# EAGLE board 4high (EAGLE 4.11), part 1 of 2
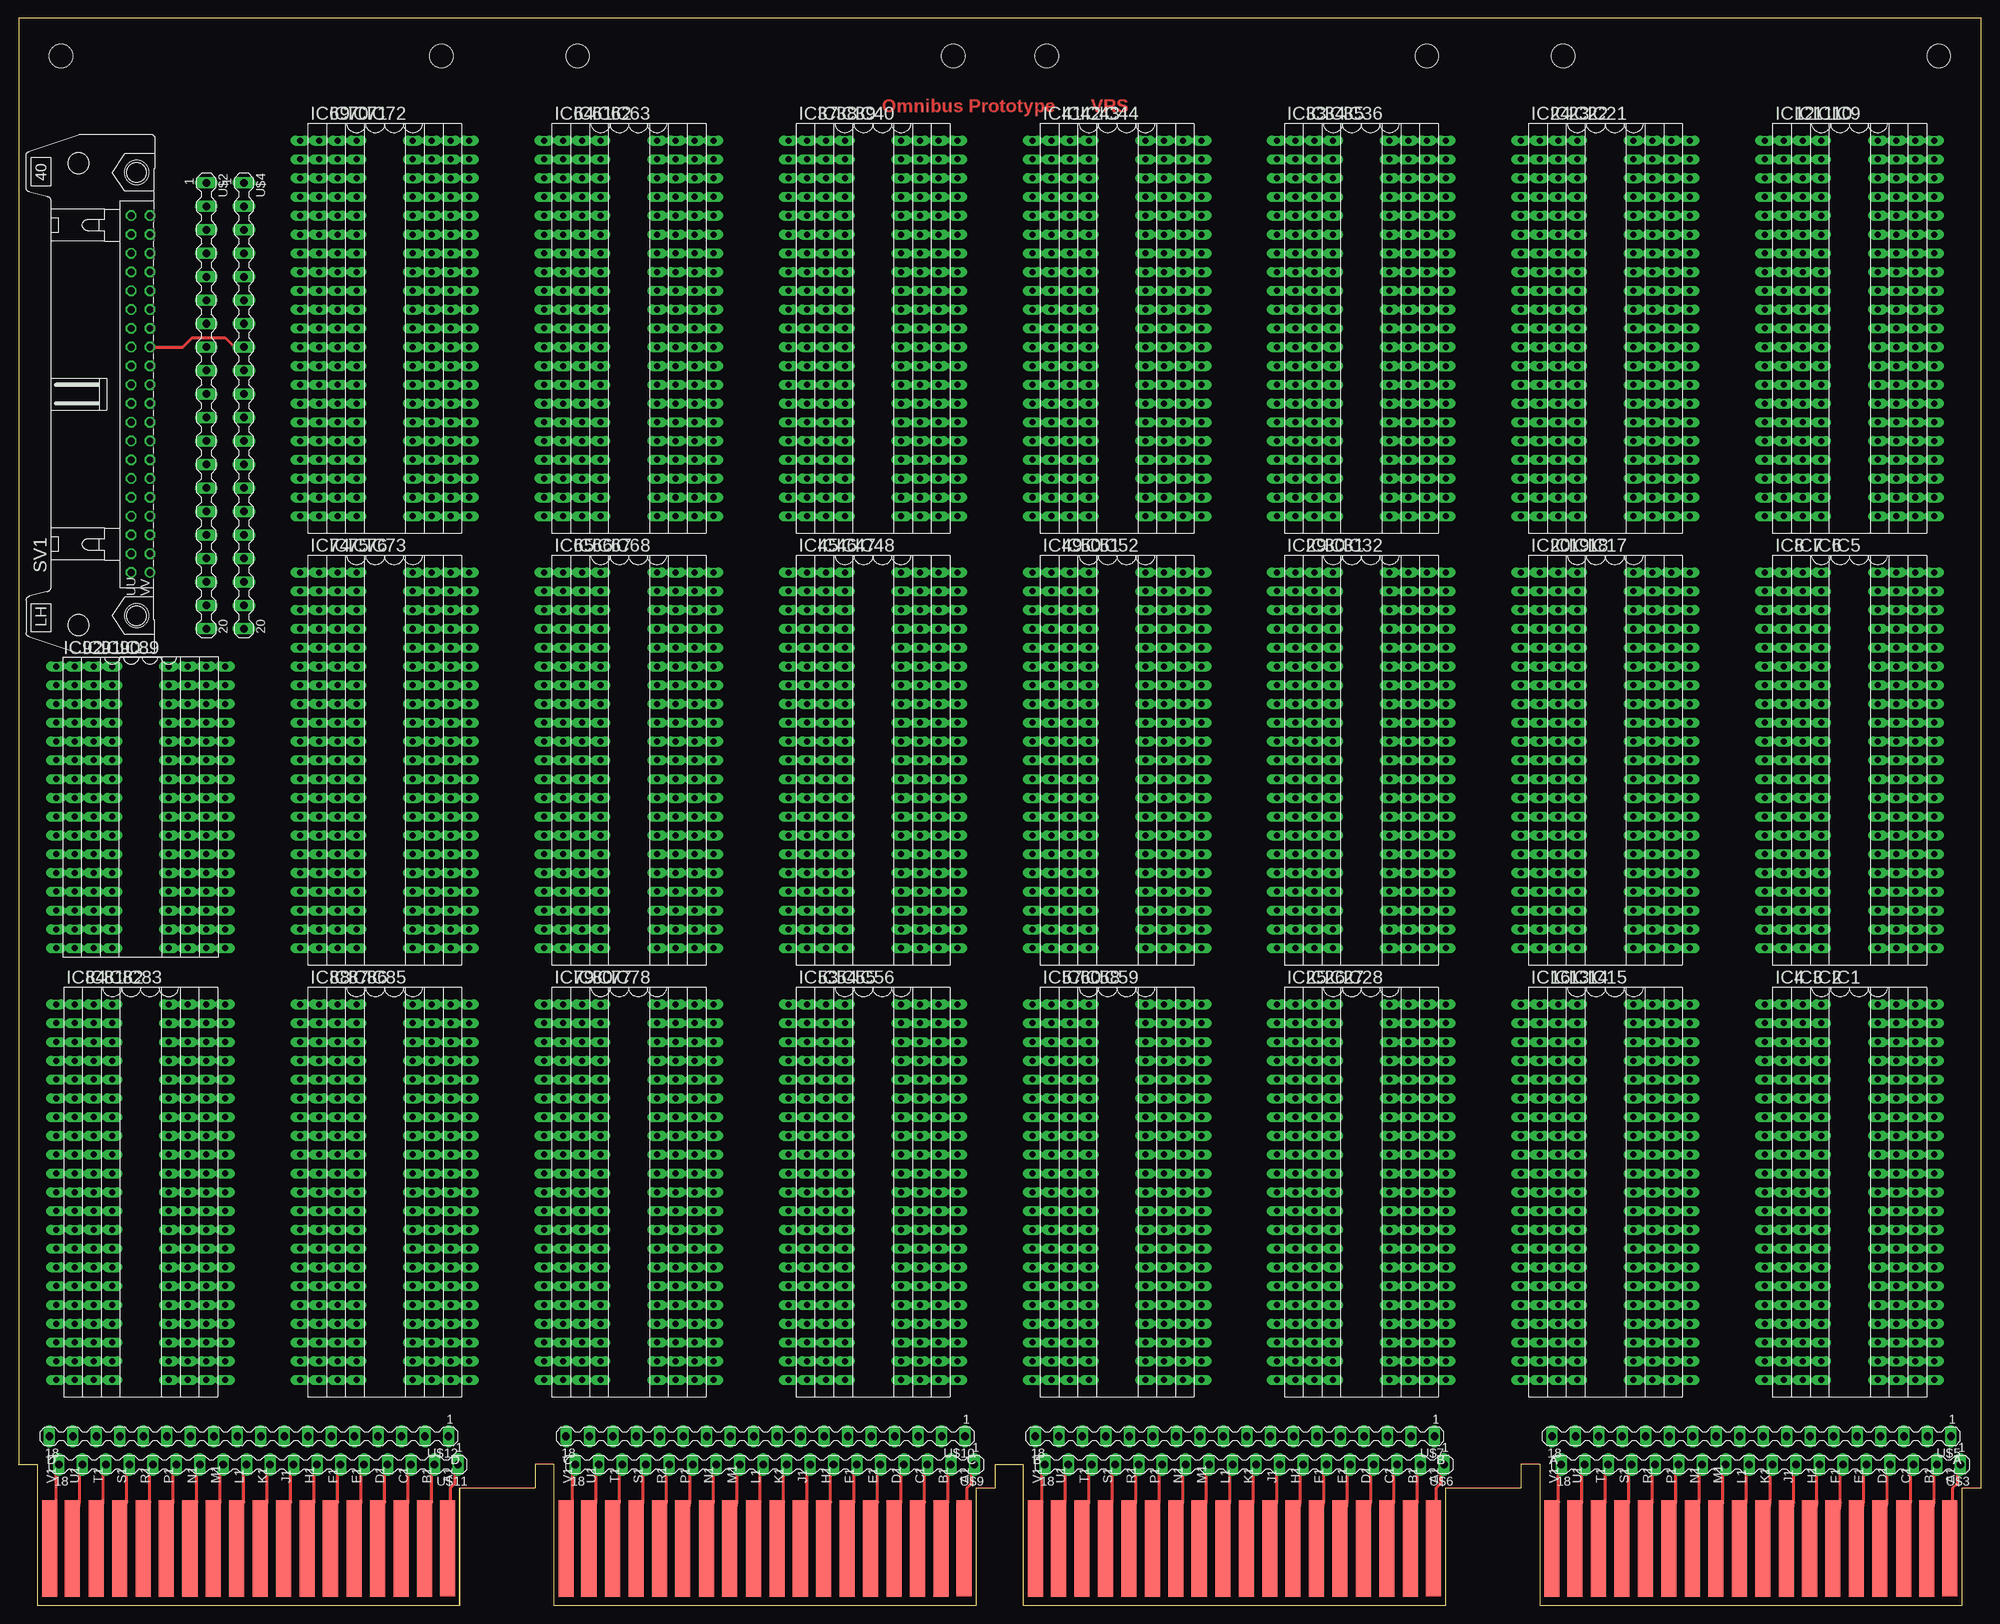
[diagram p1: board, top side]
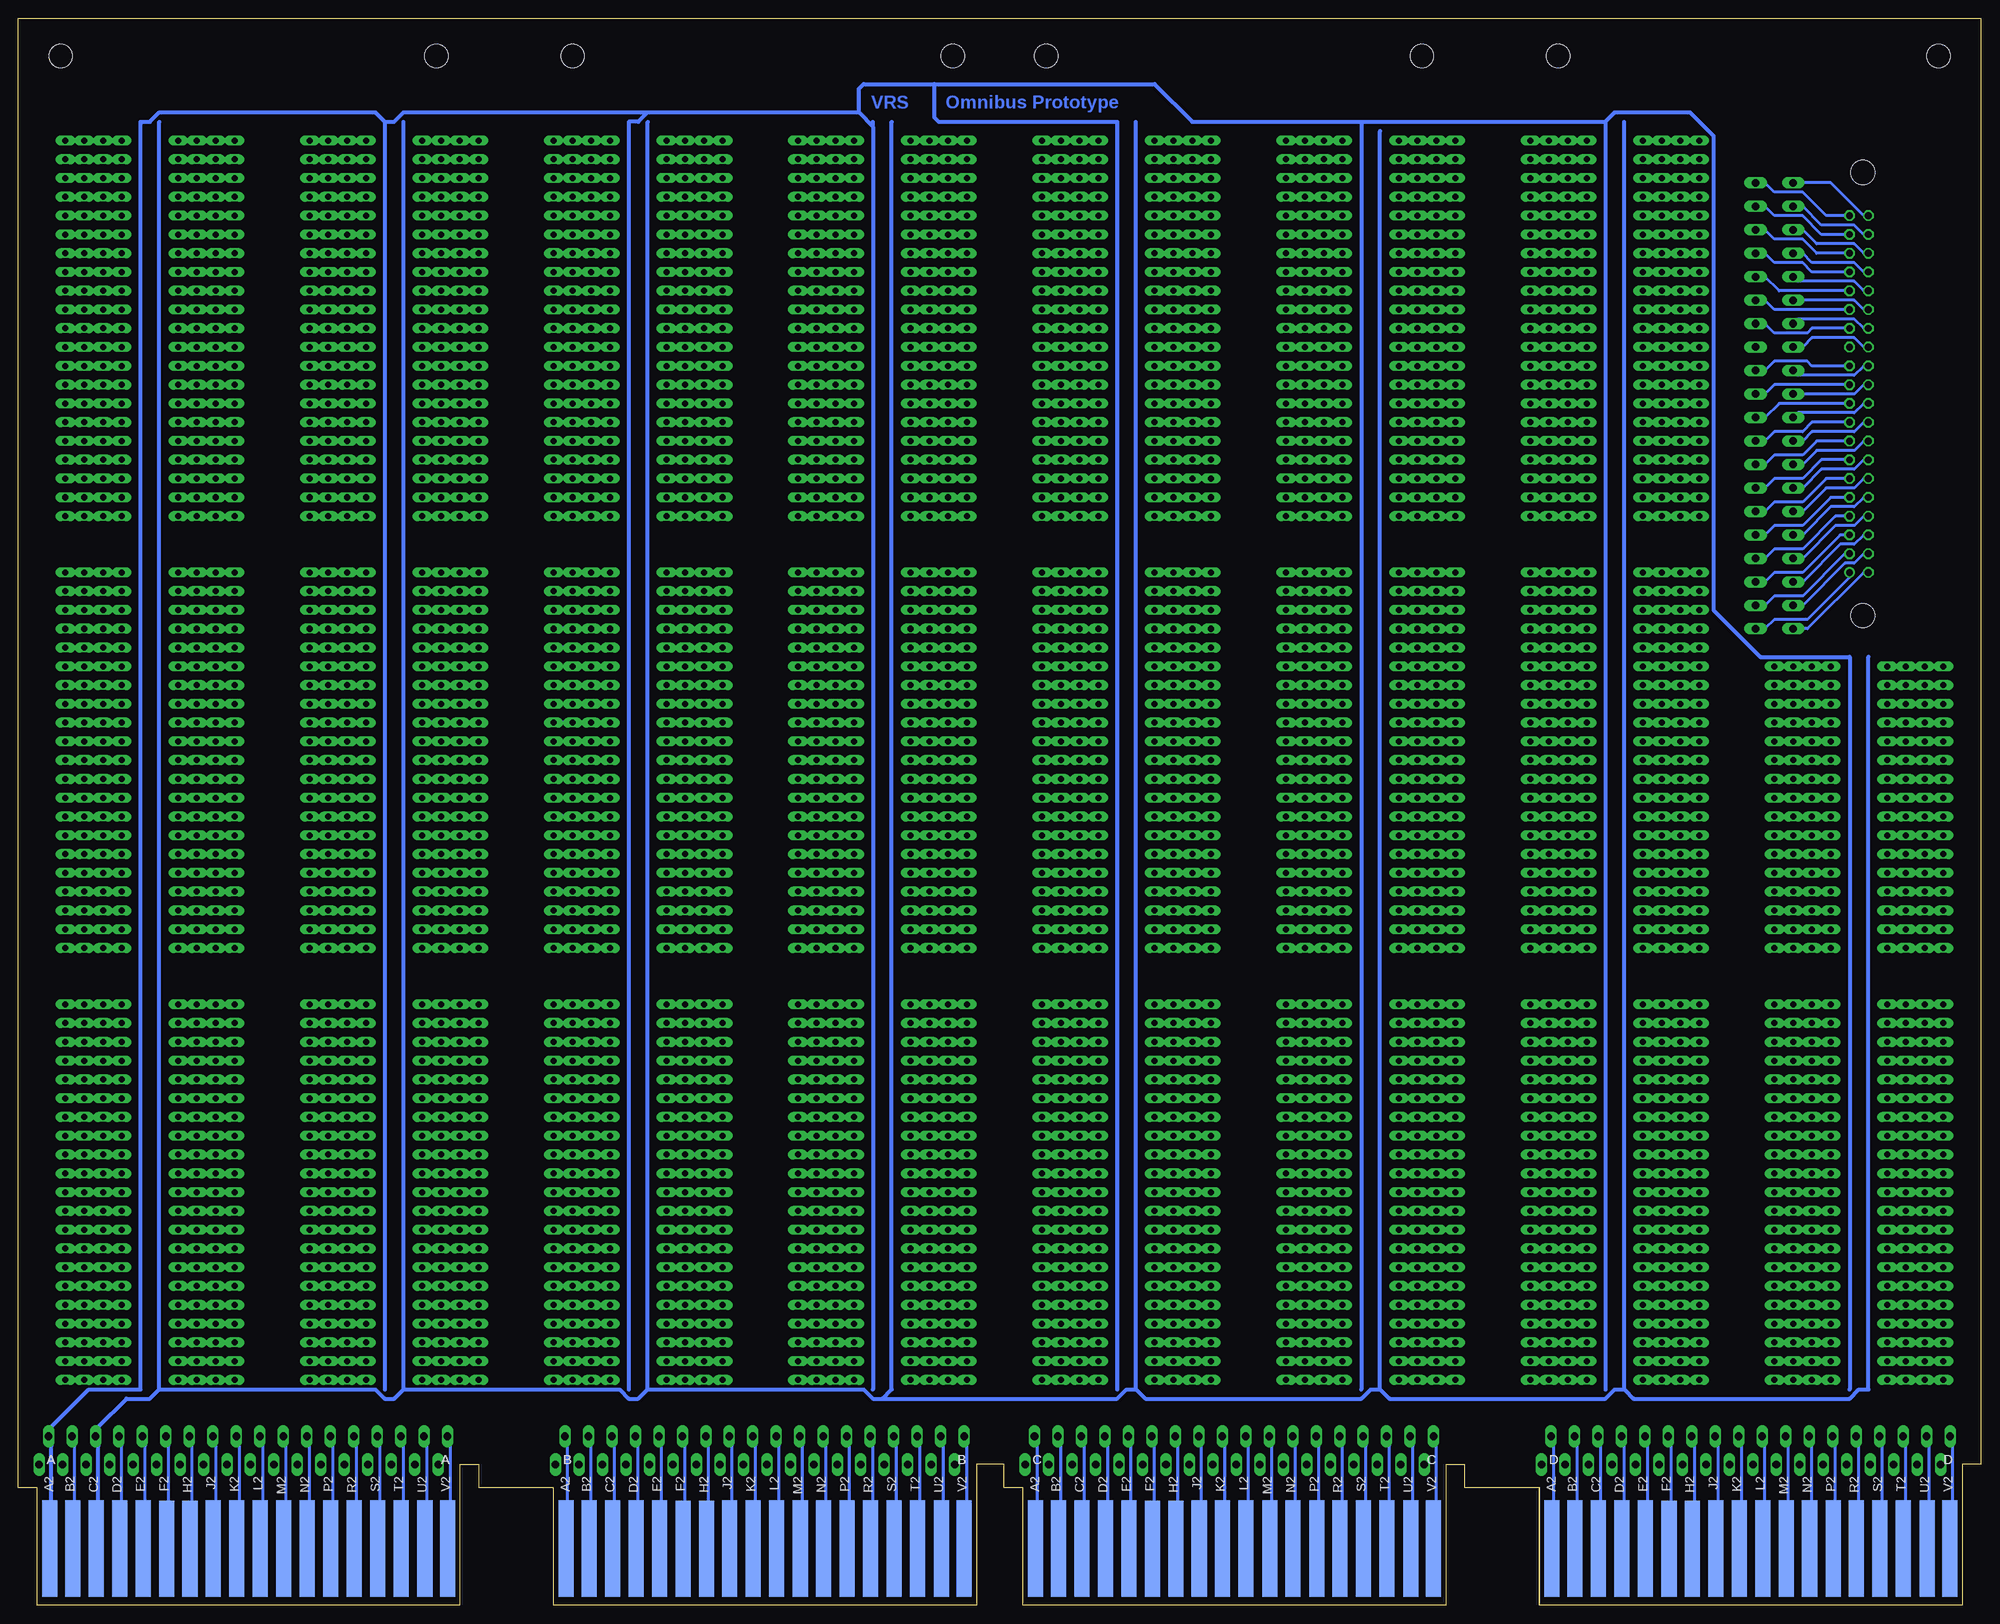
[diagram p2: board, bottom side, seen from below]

Size 265.43 x 214.63 mm. Coordinates in mm from the lower left corner, seen from the top.
Copper layers (1*16): Top 0.035mm / dielectric 1.5mm / Bottom 0.035mm
Design rules "olimex10mil": minimum track width 15mil, minimum drill 24mil, track to track 15mil, track to pad 10mil, pad to pad 10mil, via to via 10mil, smd to smd 10mil, copper to edge 25mil, drill to drill 10mil, minimum pad ring 10mil, minimum via ring 8mil, stop-mask expansion 0mil, vias tented up to drill 0mil, thermal gap 10mil
Net classes: 1 supply: width 0.508 mm

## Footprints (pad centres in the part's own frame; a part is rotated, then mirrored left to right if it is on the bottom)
DIL42 = drill 0.813 long: 1 -25.4,-7.62; 2 -22.86,-7.62; 3 -20.32,-7.62; 4 -17.78,-7.62; 5 -15.24,-7.62; 6 -12.7,-7.62; 7 -10.16,-7.62; 8 -7.62,-7.62; 9 -5.08,-7.62; 10 -2.54,-7.62; 11 0,-7.62; 12 2.54,-7.62; 13 5.08,-7.62; 14 7.62,-7.62; 15 10.16,-7.62; 16 12.7,-7.62; 17 15.24,-7.62; 18 17.78,-7.62; 19 20.32,-7.62; 20 22.86,-7.62; 21 25.4,-7.62; 22 25.4,7.62; 23 22.86,7.62; 24 20.32,7.62; 25 17.78,7.62; 26 15.24,7.62; 27 12.7,7.62; 28 10.16,7.62; 29 7.62,7.62; 30 5.08,7.62; 31 2.54,7.62; 32 0,7.62; 33 -2.54,7.62; 34 -5.08,7.62; 35 -7.62,7.62; 36 -10.16,7.62; 37 -12.7,7.62; 38 -15.24,7.62; 39 -17.78,7.62; 40 -20.32,7.62; 41 -22.86,7.62; 42 -25.4,7.62
DIL32 = drill 0.813 long: 1 -19.05,-7.62; 2 -16.51,-7.62; 3 -13.97,-7.62; 4 -11.43,-7.62; 5 -8.89,-7.62; 6 -6.35,-7.62; 7 -3.81,-7.62; 8 -1.27,-7.62; 9 1.27,-7.62; 10 3.81,-7.62; 11 6.35,-7.62; 12 8.89,-7.62; 13 11.43,-7.62; 14 13.97,-7.62; 15 16.51,-7.62; 16 19.05,-7.62; 17 19.05,7.62; 18 16.51,7.62; 19 13.97,7.62; 20 11.43,7.62; 21 8.89,7.62; 22 6.35,7.62; 23 3.81,7.62; 24 1.27,7.62; 25 -1.27,7.62; 26 -3.81,7.62; 27 -6.35,7.62; 28 -8.89,7.62; 29 -11.43,7.62; 30 -13.97,7.62; 31 -16.51,7.62; 32 -19.05,7.62
DEC40PINH = drill 0.914 octagon: A 24.13,1.27; AA -3.81,1.27; B 24.13,-1.27; BB -3.81,-1.27; C 21.59,1.27; CC -6.35,1.27; D 21.59,-1.27; DD -6.35,-1.27; E 19.05,1.27; EE -8.89,1.27; F 19.05,-1.27; FF -8.89,-1.27; H 16.51,1.27; HH -11.43,1.27; J 16.51,-1.27; JJ -11.43,-1.27; K 13.97,1.27; KK -13.97,1.27; L 13.97,-1.27; LL -13.97,-1.27; M 11.43,1.27; MM -16.51,1.27; N 11.43,-1.27; NN -16.51,-1.27; P 8.89,1.27; PP -19.05,1.27; R 8.89,-1.27; RR -19.05,-1.27; S 6.35,1.27; SS -21.59,1.27; T 6.35,-1.27; TT -21.59,-1.27; U 3.81,1.27; UU -24.13,1.27; V 3.81,-1.27; W 1.27,1.27; X 1.27,-1.27; Y -1.27,1.27; Z -1.27,-1.27 | drill 0.914 round: VV -24.13,-1.27 | hole 3.302: -29.972,0.533; 29.972,0.533
EDGE-CON8 = smd 2.032 x 13.017: AA1 261.223,7.709; AB1 258.118,7.684; AC1 254.956,7.684; AD1 251.765,7.684; AE1 248.59,7.693; AF1 245.389,7.668; AH1 242.24,7.668; AJ1 239.09,7.668; AK1 235.915,7.668; AL1 232.74,7.693; AM1 229.54,7.693; AN1 226.39,7.693; AP1 223.19,7.668; AR1 220.04,7.668; AS1 216.865,7.693; AT1 213.69,7.693; AU1 210.49,7.693; AV1 207.404,7.668; BA1 191.373,7.709; BB1 188.268,7.684; BC1 185.106,7.684; BD1 181.915,7.684; BE1 178.74,7.693; BF1 175.539,7.668; BH1 172.39,7.668; BJ1 169.24,7.668; BK1 166.065,7.668; BL1 162.89,7.693; BM1 159.69,7.693; BN1 156.54,7.693; BP1 153.34,7.668; BR1 150.19,7.668; BS1 147.015,7.693; BT1 143.84,7.693; BU1 140.64,7.693; BV1 137.554,7.668; CA1 127.873,7.709; CB1 124.768,7.684; CC1 121.606,7.684; CD1 118.415,7.684; CE1 115.24,7.693; CF1 112.039,7.668; CH1 108.89,7.668; CJ1 105.74,7.668; CK1 102.565,7.668; CL1 99.39,7.693; CM1 96.19,7.693; CN1 93.04,7.693; CP1 89.84,7.668; CR1 86.69,7.668; CS1 83.515,7.693; CT1 80.34,7.693; CU1 77.14,7.693; CV1 74.054,7.668; DA1 58.023,7.709; DB1 54.918,7.684; DC1 51.756,7.684; DD1 48.565,7.684; DE1 45.39,7.693; DF1 42.189,7.668; DH1 39.04,7.668; DJ1 35.89,7.668; DK1 32.715,7.668; DL1 29.54,7.693; DM1 26.34,7.693; DN1 23.19,7.693; DP1 19.99,7.668; DR1 16.84,7.668; DS1 13.665,7.693; DT1 10.49,7.693; DU1 7.29,7.693; DV1 4.204,7.668 | smd 2.032 x 13.017 bottom: AA2 261.223,7.69; AB2 258.102,7.668; AC2 254.94,7.668; AD2 251.765,7.693; AE2 248.59,7.693; AF2 245.389,7.642; AH2 242.24,7.642; AJ2 239.09,7.668; AK2 235.915,7.668; AL2 232.74,7.693; AM2 229.54,7.693; AN2 226.39,7.693; AP2 223.19,7.668; AR2 220.04,7.668; AS2 216.865,7.693; AT2 213.69,7.693; AU2 210.464,7.693; AV2 207.404,7.668; BA2 191.373,7.69; BB2 188.252,7.668; BC2 185.09,7.668; BD2 181.915,7.693; BE2 178.74,7.693; BF2 175.539,7.642; BH2 172.39,7.642; BJ2 169.24,7.668; BK2 166.065,7.668; BL2 162.89,7.693; BM2 159.69,7.693; BN2 156.54,7.693; BP2 153.34,7.668; BR2 150.19,7.668; BS2 147.015,7.693; BT2 143.84,7.693; BU2 140.614,7.693; BV2 137.554,7.668; CA2 127.873,7.69; CB2 124.752,7.668; CC2 121.59,7.668; CD2 118.415,7.693; CE2 115.24,7.693; CF2 112.039,7.642; CH2 108.89,7.642; CJ2 105.74,7.668; CK2 102.565,7.668; CL2 99.39,7.693; CM2 96.19,7.693; CN2 93.04,7.693; CP2 89.84,7.668; CR2 86.69,7.668; CS2 83.515,7.693; CT2 80.34,7.693; CU2 77.114,7.693; CV2 74.054,7.668; DA2 58.023,7.69; DB2 54.902,7.668; DC2 51.74,7.668; DD2 48.565,7.693; DE2 45.39,7.693; DF2 42.189,7.642; DH2 39.04,7.642; DJ2 35.89,7.668; DK2 32.715,7.668; DL2 29.54,7.693; DM2 26.34,7.693; DN2 23.19,7.693; DP2 19.99,7.668; DR2 16.84,7.668; DS2 13.665,7.693; DT2 10.49,7.693; DU2 7.264,7.693; DV2 4.204,7.668
MA20-1 = drill 1.016 long: 1 -28.575,0; 2 -25.4,0; 3 -22.225,0; 4 -19.05,0; 5 -15.875,0; 6 -12.7,0; 7 -9.525,0; 8 -6.35,0; 9 -3.175,0; 10 0,0; 11 3.175,0; 12 6.35,0; 13 9.525,0; 14 12.7,0; 15 15.875,0; 16 19.05,0; 17 22.225,0; 18 25.4,0; 19 28.575,0; 20 31.75,0
MA18-1 = drill 1.016 long: 1 -25.146,0; 2 -21.971,0; 3 -18.796,0; 4 -15.621,0; 5 -12.446,0; 6 -9.271,0; 7 -6.096,0; 8 -2.921,0; 9 0.254,0; 10 3.429,0; 11 6.604,0; 12 9.779,0; 13 12.954,0; 14 16.129,0; 15 19.304,0; 16 22.479,0; 17 25.654,0; 18 28.829,0
OMNIBUS = hole 3.175: 208.915,209.55; 259.715,209.55; 190.5,209.55; 139.065,209.55; 75.616,209.55; 126.416,209.55; 57.201,209.55; 5.766,209.55

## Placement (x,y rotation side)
IC1  [DIL42]  251.46,55.88 270 top
IC2  [DIL42]  248.92,55.88 270 top
IC3  [DIL42]  246.38,55.88 270 top
IC4  [DIL42]  243.84,55.88 270 top
IC5  [DIL42]  251.46,114.3 270 top
IC6  [DIL42]  248.92,114.3 270 top
IC7  [DIL42]  246.38,114.3 270 top
IC8  [DIL42]  243.84,114.3 270 top
IC9  [DIL42]  251.46,172.72 270 top
IC10  [DIL42]  248.92,172.72 270 top
IC11  [DIL42]  246.38,172.72 270 top
IC12  [DIL42]  243.84,172.72 270 top
IC13  [DIL42]  213.36,55.88 270 top
IC14  [DIL42]  215.9,55.88 270 top
IC15  [DIL42]  218.44,55.88 270 top
IC16  [DIL42]  210.82,55.88 270 top
IC17  [DIL42]  218.44,114.3 270 top
IC18  [DIL42]  215.9,114.3 270 top
IC19  [DIL42]  213.36,114.3 270 top
IC20  [DIL42]  210.82,114.3 270 top
IC21  [DIL42]  218.44,172.72 270 top
IC22  [DIL42]  215.9,172.72 270 top
IC23  [DIL42]  213.36,172.72 270 top
IC24  [DIL42]  210.82,172.72 270 top
IC25  [DIL42]  177.8,55.88 270 top
IC26  [DIL42]  180.34,55.88 270 top
IC27  [DIL42]  182.88,55.88 270 top
IC28  [DIL42]  185.42,55.88 270 top
IC29  [DIL42]  177.8,114.3 270 top
IC30  [DIL42]  180.34,114.3 270 top
IC31  [DIL42]  182.88,114.3 270 top
IC32  [DIL42]  185.42,114.3 270 top
IC33  [DIL42]  177.8,172.72 270 top
IC34  [DIL42]  180.34,172.72 270 top
IC35  [DIL42]  182.88,172.72 270 top
IC36  [DIL42]  185.42,172.72 270 top
IC37  [DIL42]  111.76,172.72 270 top
IC38  [DIL42]  114.3,172.72 270 top
IC39  [DIL42]  116.84,172.72 270 top
IC40  [DIL42]  119.38,172.72 270 top
IC41  [DIL42]  144.78,172.72 270 top
IC42  [DIL42]  147.32,172.72 270 top
IC43  [DIL42]  149.86,172.72 270 top
IC44  [DIL42]  152.4,172.72 270 top
IC45  [DIL42]  111.76,114.3 270 top
IC46  [DIL42]  114.3,114.3 270 top
IC47  [DIL42]  116.84,114.3 270 top
IC48  [DIL42]  119.38,114.3 270 top
IC49  [DIL42]  144.78,114.3 270 top
IC50  [DIL42]  147.32,114.3 270 top
IC51  [DIL42]  149.86,114.3 270 top
IC52  [DIL42]  152.4,114.3 270 top
IC53  [DIL42]  111.76,55.88 270 top
IC54  [DIL42]  114.3,55.88 270 top
IC55  [DIL42]  116.84,55.88 270 top
IC56  [DIL42]  119.38,55.88 270 top
IC57  [DIL42]  144.78,55.88 270 top
IC58  [DIL42]  149.86,55.88 270 top
IC59  [DIL42]  152.4,55.88 270 top
IC60  [DIL42]  147.32,55.88 270 top
IC61  [DIL42]  81.28,172.72 270 top
IC62  [DIL42]  83.82,172.72 270 top
IC63  [DIL42]  86.36,172.72 270 top
IC64  [DIL42]  78.74,172.72 270 top
IC65  [DIL42]  78.74,114.3 270 top
IC66  [DIL42]  81.28,114.3 270 top
IC67  [DIL42]  83.82,114.3 270 top
IC68  [DIL42]  86.36,114.3 270 top
IC69  [DIL42]  45.72,172.72 270 top
IC70  [DIL42]  48.26,172.72 270 top
IC71  [DIL42]  50.8,172.72 270 top
IC72  [DIL42]  53.34,172.72 270 top
IC73  [DIL42]  53.34,114.3 270 top
IC74  [DIL42]  45.72,114.3 270 top
IC75  [DIL42]  48.26,114.3 270 top
IC76  [DIL42]  50.8,114.3 270 top
IC77  [DIL42]  83.82,55.88 270 top
IC78  [DIL42]  86.36,55.88 270 top
IC79  [DIL42]  78.74,55.88 270 top
IC80  [DIL42]  81.28,55.88 270 top
IC81  [DIL42]  15.24,55.88 270 top
IC82  [DIL42]  17.78,55.88 270 top
IC83  [DIL42]  20.32,55.88 270 top
IC84  [DIL42]  12.7,55.88 270 top
IC85  [DIL42]  53.34,55.88 270 top
IC86  [DIL42]  50.8,55.88 270 top
IC87  [DIL42]  48.26,55.88 270 top
IC88  [DIL42]  45.72,55.88 270 top
IC89  [DIL32]  20.32,107.95 270 top
IC90  [DIL32]  17.78,107.95 270 top
IC91  [DIL32]  15.24,107.95 270 top
IC92  [DIL32]  12.7,107.95 270 top
SV1  [DEC40PINH]  16.51,163.83 90 top
U$1  [EDGE-CON8]  0,0 0 top
U$2  MA20-1  [MA20-1]  25.4,163.83 270 top
U$3  MA18-1  [MA18-1]  237.49,19.05 180 top
U$4  MA20-1  [MA20-1]  30.48,163.83 270 top
U$5  MA18-1  [MA18-1]  236.22,22.86 180 top
U$6  MA18-1  [MA18-1]  167.64,19.05 180 top
U$7  MA18-1  [MA18-1]  166.37,22.86 180 top
U$8  OUTLINE-OMNIBUS  [OMNIBUS]  0,0 0 top
U$9  MA18-1  [MA18-1]  104.14,19.05 180 top
U$10  MA18-1  [MA18-1]  102.87,22.86 180 top
U$11  MA18-1  [MA18-1]  34.29,19.05 180 top
U$12  MA18-1  [MA18-1]  33.02,22.86 180 top

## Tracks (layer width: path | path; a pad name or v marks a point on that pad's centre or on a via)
GND
  Bottom 0.508: U$1.AC2 254.63,13.97 254.63,21.59 U$5.3 254.63,24.13 250.82,27.94 247.65,27.94 246.38,29.21 | 15.24,128.27 15.24,29.21 16.51,29.21 17.78,27.94 46.99,27.94 48.26,29.21 | 48.26,29.21 48.26,200.66 | 81.28,29.21 81.28,199.39 | 114.3,29.21 114.3,200.66 | 147.32,200.66 147.32,29.21 148.59,27.94 | 180.34,29.21 180.34,200.66 | 213.36,29.21 213.36,200.66 | 246.38,29.21 246.38,200.66 | 48.26,29.21 49.53,29.21 50.8,27.94 80.01,27.94 81.28,29.21 | 81.28,29.21 82.55,29.21 83.82,27.94 113.03,27.94 114.3,29.21 | 246.38,29.21 217.17,29.21 215.9,27.94 214.63,27.94 213.36,29.21 | 213.36,29.21 184.15,29.21 182.88,27.94 181.61,27.94 180.34,29.21 | 180.34,29.21 151.13,29.21 149.86,27.94 148.59,27.94 | 114.3,29.21 115.57,29.21 116.84,27.94 148.59,27.94
N$1
  Bottom 0.381: IC4.1 IC3.1 IC2.1 IC1.1
N$2
  Bottom 0.381: IC4.2 IC3.2 IC2.2 IC1.2
N$3
  Bottom 0.381: IC4.3 IC3.3 IC2.3 IC1.3
N$4
  Bottom 0.381: IC4.4 IC3.4 IC2.4 IC1.4
N$5
  Bottom 0.381: IC4.5 IC3.5 IC2.5 IC1.5
N$6
  Bottom 0.381: IC4.6 IC3.6 IC2.6 IC1.6
N$7
  Bottom 0.381: IC4.7 IC3.7 IC2.7 IC1.7
N$8
  Bottom 0.381: IC4.8 IC3.8 IC2.8 IC1.8
N$9
  Bottom 0.381: IC4.9 IC3.9 IC2.9 IC1.9
N$10
  Bottom 0.381: IC4.10 IC3.10 IC2.10 IC1.10
N$11
  Bottom 0.381: IC4.11 IC3.11 IC2.11 IC1.11
N$12
  Bottom 0.381: IC4.12 IC3.12 IC2.12 IC1.12
N$13
  Bottom 0.381: IC4.13 IC3.13 IC2.13 IC1.13
N$14
  Bottom 0.381: IC4.14 IC3.14 IC2.14 IC1.14
N$15
  Bottom 0.381: IC4.15 IC3.15 IC2.15 IC1.15
N$16
  Bottom 0.381: IC4.16 IC3.16 IC2.16 IC1.16
N$17
  Bottom 0.381: IC4.17 IC3.17 IC2.17 IC1.17
N$18
  Bottom 0.381: IC4.18 IC3.18 IC2.18 IC1.18
N$19
  Bottom 0.381: IC4.19 IC3.19 IC2.19 IC1.19
N$20
  Bottom 0.381: IC4.20 IC3.20 IC2.20 IC1.20
N$21
  Bottom 0.381: IC4.21 IC3.21 IC2.21 IC1.21
N$22
  Bottom 0.381: IC4.22 IC3.22 IC2.22 IC1.22
N$23
  Bottom 0.381: IC4.23 IC3.23 IC2.23 IC1.23
N$24
  Bottom 0.381: IC4.24 IC3.24 IC2.24 IC1.24
N$25
  Bottom 0.381: IC4.25 IC3.25 IC2.25 IC1.25
N$26
  Bottom 0.381: IC4.26 IC3.26 IC2.26 IC1.26
N$27
  Bottom 0.381: IC4.27 IC3.27 IC2.27 IC1.27
N$28
  Bottom 0.381: IC4.28 IC3.28 IC2.28 IC1.28
N$29
  Bottom 0.381: IC4.29 IC3.29 IC2.29 IC1.29
N$30
  Bottom 0.381: IC4.30 IC3.30 IC2.30 IC1.30
N$31
  Bottom 0.381: IC4.31 IC3.31 IC2.31 IC1.31
N$32
  Bottom 0.381: IC4.32 IC3.32 IC2.32 IC1.32
N$33
  Bottom 0.381: IC4.33 IC3.33 IC2.33 IC1.33
N$34
  Bottom 0.381: IC4.34 IC3.34 IC2.34 IC1.34
N$35
  Bottom 0.381: IC4.35 IC3.35 IC2.35 IC1.35
N$36
  Bottom 0.381: IC4.36 IC3.36 IC2.36 IC1.36
N$37
  Bottom 0.381: IC4.37 IC3.37 IC2.37 IC1.37
N$38
  Bottom 0.381: IC4.38 IC3.38 IC2.38 IC1.38
N$39
  Bottom 0.381: IC4.39 IC3.39 IC2.39 IC1.39
N$40
  Bottom 0.381: IC4.40 IC3.40 IC2.40 IC1.40
N$41
  Bottom 0.381: IC4.41 IC3.41 IC2.41 IC1.41
N$42
  Bottom 0.381: IC4.42 IC3.42 IC2.42 IC1.42
N$43
  Bottom 0.381: IC8.1 IC7.1 IC6.1 IC5.1
N$44
  Bottom 0.381: IC8.2 IC7.2 IC6.2 IC5.2
N$45
  Bottom 0.381: IC8.3 IC7.3 IC6.3 IC5.3
N$46
  Bottom 0.381: IC8.4 IC7.4 IC6.4 IC5.4
N$47
  Bottom 0.381: IC8.5 IC7.5 IC6.5 IC5.5
N$48
  Bottom 0.381: IC8.6 IC7.6 IC6.6 IC5.6
N$49
  Bottom 0.381: IC8.7 IC7.7 IC6.7 IC5.7
N$50
  Bottom 0.381: IC8.8 IC7.8 IC6.8 IC5.8
N$51
  Bottom 0.381: IC8.9 IC7.9 IC6.9 IC5.9
N$52
  Bottom 0.381: IC8.10 IC7.10 IC6.10 IC5.10
N$53
  Bottom 0.381: IC8.11 IC7.11 IC6.11 IC5.11
N$54
  Bottom 0.381: IC8.12 IC7.12 IC6.12 IC5.12
N$55
  Bottom 0.381: IC8.13 IC7.13 IC6.13 IC5.13
N$56
  Bottom 0.381: IC8.14 IC7.14 IC6.14 IC5.14
N$57
  Bottom 0.381: IC8.15 IC7.15 IC6.15 IC5.15
N$58
  Bottom 0.381: IC8.16 IC7.16 IC6.16 IC5.16
N$59
  Bottom 0.381: IC8.17 IC7.17 IC6.17 IC5.17
N$60
  Bottom 0.381: IC8.18 IC7.18 IC6.18 IC5.18
N$61
  Bottom 0.381: IC8.19 IC7.19 IC6.19 IC5.19
N$62
  Bottom 0.381: IC8.20 IC7.20 IC6.20 IC5.20
N$63
  Bottom 0.381: IC8.21 IC7.21 IC6.21 IC5.21
N$64
  Bottom 0.381: IC8.22 IC7.22 IC6.22 IC5.22
N$65
  Bottom 0.381: IC8.23 IC7.23 IC6.23 IC5.23
N$66
  Bottom 0.381: IC8.24 IC7.24 IC6.24 IC5.24
N$67
  Bottom 0.381: IC8.25 IC7.25 IC6.25 IC5.25
N$68
  Bottom 0.381: IC8.26 IC7.26 IC6.26 IC5.26
N$69
  Bottom 0.381: IC8.27 IC7.27 IC6.27 IC5.27
N$70
  Bottom 0.381: IC8.28 IC7.28 IC6.28 IC5.28
N$71
  Bottom 0.381: IC8.29 IC7.29 IC6.29 IC5.29
N$72
  Bottom 0.381: IC8.30 IC7.30 IC6.30 IC5.30
N$73
  Bottom 0.381: IC8.31 IC7.31 IC6.31 IC5.31
N$74
  Bottom 0.381: IC8.32 IC7.32 IC6.32 IC5.32
N$75
  Bottom 0.381: IC8.33 IC7.33 IC6.33 IC5.33
N$76
  Bottom 0.381: IC8.34 IC7.34 IC6.34 IC5.34
N$77
  Bottom 0.381: IC8.35 IC7.35 IC6.35 IC5.35
N$78
  Bottom 0.381: IC8.36 IC7.36 IC6.36 IC5.36
N$79
  Bottom 0.381: IC8.37 IC7.37 IC6.37 IC5.37
N$80
  Bottom 0.381: IC8.38 IC7.38 IC6.38 IC5.38
N$81
  Bottom 0.381: IC8.39 IC7.39 IC6.39 IC5.39
N$82
  Bottom 0.381: IC8.40 IC7.40 IC6.40 IC5.40
N$83
  Bottom 0.381: IC8.41 IC7.41 IC6.41 IC5.41
N$84
  Bottom 0.381: IC8.42 IC7.42 IC6.42 IC5.42
N$85
  Bottom 0.381: IC12.1 IC11.1 IC10.1 IC9.1
N$86
  Bottom 0.381: IC12.2 IC11.2 IC10.2 IC9.2
N$87
  Bottom 0.381: IC12.3 IC11.3 IC10.3 IC9.3
N$88
  Bottom 0.381: IC12.4 IC11.4 IC10.4 IC9.4
N$89
  Bottom 0.381: IC12.5 IC11.5 IC10.5 IC9.5
N$90
  Bottom 0.381: IC12.6 IC11.6 IC10.6 IC9.6
N$91
  Bottom 0.381: IC12.7 IC11.7 IC10.7 IC9.7
N$92
  Bottom 0.381: IC12.8 IC11.8 IC10.8 IC9.8
N$93
  Bottom 0.381: IC12.9 IC11.9 IC10.9 IC9.9
N$94
  Bottom 0.381: IC12.10 IC11.10 IC10.10 IC9.10
N$95
  Bottom 0.381: IC12.11 IC11.11 IC10.11 IC9.11
N$96
  Bottom 0.381: IC12.12 IC11.12 IC10.12 IC9.12
N$97
  Bottom 0.381: IC12.13 IC11.13 IC10.13 IC9.13
N$98
  Bottom 0.381: IC12.14 IC11.14 IC10.14 IC9.14
N$99
  Bottom 0.381: IC12.15 IC11.15 IC10.15 IC9.15
N$100
  Bottom 0.381: IC12.16 IC11.16 IC10.16 IC9.16
N$101
  Bottom 0.381: IC12.17 IC11.17 IC10.17 IC9.17
N$102
  Bottom 0.381: IC12.18 IC11.18 IC10.18 IC9.18
N$103
  Bottom 0.381: IC12.19 IC11.19 IC10.19 IC9.19
N$104
  Bottom 0.381: IC12.20 IC11.20 IC10.20 IC9.20
N$105
  Bottom 0.381: IC12.21 IC11.21 IC10.21 IC9.21
N$106
  Bottom 0.381: IC12.22 IC11.22 IC10.22 IC9.22
N$107
  Bottom 0.381: IC12.23 IC11.23 IC10.23 IC9.23
N$108
  Bottom 0.381: IC12.24 IC11.24 IC10.24 IC9.24
N$109
  Bottom 0.381: IC12.25 IC11.25 IC10.25 IC9.25
N$110
  Bottom 0.381: IC12.26 IC11.26 IC10.26 IC9.26
N$111
  Bottom 0.381: IC12.27 IC11.27 IC10.27 IC9.27
N$112
  Bottom 0.381: IC12.28 IC11.28 IC10.28 IC9.28
N$113
  Bottom 0.381: IC12.29 IC11.29 IC10.29 IC9.29
N$114
  Bottom 0.381: IC12.30 IC11.30 IC10.30 IC9.30
N$115
  Bottom 0.381: IC12.31 IC11.31 IC10.31 IC9.31
N$116
  Bottom 0.381: IC12.32 IC11.32 IC10.32 IC9.32
N$117
  Bottom 0.381: IC12.33 IC11.33 IC10.33 IC9.33
N$118
  Bottom 0.381: IC12.34 IC11.34 IC10.34 IC9.34
N$119
  Bottom 0.381: IC12.35 IC11.35 IC10.35 IC9.35
N$120
  Bottom 0.381: IC12.36 IC11.36 IC10.36 IC9.36
N$121
  Bottom 0.381: IC12.37 IC11.37 IC10.37 IC9.37
N$122
  Bottom 0.381: IC12.38 IC11.38 IC10.38 IC9.38
N$123
  Bottom 0.381: IC12.39 IC11.39 IC10.39 IC9.39
N$124
  Bottom 0.381: IC12.40 IC11.40 IC10.40 IC9.40
N$125
  Bottom 0.381: IC12.41 IC11.41 IC10.41 IC9.41
N$126
  Bottom 0.381: IC12.42 IC11.42 IC10.42 IC9.42
N$127
  Bottom 0.381: IC16.1 IC13.1 IC14.1 IC15.1
N$128
  Bottom 0.381: IC16.2 IC13.2 IC14.2 IC15.2
N$129
  Bottom 0.381: IC16.3 IC13.3 IC14.3 IC15.3
N$130
  Bottom 0.381: IC16.4 IC13.4 IC14.4 IC15.4
N$131
  Bottom 0.381: IC16.5 IC13.5 IC14.5 IC15.5
N$132
  Bottom 0.381: IC16.6 IC13.6 IC14.6 IC15.6
N$133
  Bottom 0.381: IC16.7 IC13.7 IC14.7 IC15.7
N$134
  Bottom 0.381: IC16.8 IC13.8 IC14.8 IC15.8
N$135
  Bottom 0.381: IC16.9 IC13.9 IC14.9 IC15.9
N$136
  Bottom 0.381: IC16.10 IC13.10 IC14.10 IC15.10
N$137
  Bottom 0.381: IC16.11 IC13.11 IC14.11 IC15.11
N$138
  Bottom 0.381: IC16.12 IC13.12 IC14.12 IC15.12
N$139
  Bottom 0.381: IC16.13 IC13.13 IC14.13 IC15.13
N$140
  Bottom 0.381: IC16.14 IC13.14 IC14.14 IC15.14
N$141
  Bottom 0.381: IC16.15 IC13.15 IC14.15 IC15.15
N$142
  Bottom 0.381: IC16.16 IC13.16 IC14.16 IC15.16
N$143
  Bottom 0.381: IC16.17 IC13.17 IC14.17 IC15.17
N$144
  Bottom 0.381: IC16.18 IC13.18 IC14.18 IC15.18
N$145
  Bottom 0.381: IC16.19 IC13.19 IC14.19 IC15.19
N$146
  Bottom 0.381: IC16.20 IC13.20 IC14.20 IC15.20
N$147
  Bottom 0.381: IC16.21 IC13.21 IC14.21 IC15.21
N$148
  Bottom 0.381: IC16.22 IC13.22 IC14.22 IC15.22
N$149
  Bottom 0.381: IC16.23 IC13.23 IC14.23 IC15.23
N$150
  Bottom 0.381: IC16.24 IC13.24 IC14.24 IC15.24
N$151
  Bottom 0.381: IC16.25 IC13.25 IC14.25 IC15.25
N$152
  Bottom 0.381: IC16.26 IC13.26 IC14.26 IC15.26
N$153
  Bottom 0.381: IC16.27 IC13.27 IC14.27 IC15.27
N$154
  Bottom 0.381: IC16.28 IC13.28 IC14.28 IC15.28
N$155
  Bottom 0.381: IC16.29 IC13.29 IC14.29 IC15.29
N$156
  Bottom 0.381: IC16.30 IC13.30 IC14.30 IC15.30
N$157
  Bottom 0.381: IC16.31 IC13.31 IC14.31 IC15.31
N$158
  Bottom 0.381: IC16.32 IC13.32 IC14.32 IC15.32
N$159
  Bottom 0.381: IC16.33 IC13.33 IC14.33 IC15.33
N$160
  Bottom 0.381: IC16.34 IC13.34 IC14.34 IC15.34
N$161
  Bottom 0.381: IC16.35 IC13.35 IC14.35 IC15.35
N$162
  Bottom 0.381: IC16.36 IC13.36 IC14.36 IC15.36
N$163
  Bottom 0.381: IC16.37 IC13.37 IC14.37 IC15.37
N$164
  Bottom 0.381: IC16.38 IC13.38 IC14.38 IC15.38
N$165
  Bottom 0.381: IC16.39 IC13.39 IC14.39 IC15.39
N$166
  Bottom 0.381: IC16.40 IC13.40 IC14.40 IC15.40
N$167
  Bottom 0.381: IC16.41 IC13.41 IC14.41 IC15.41
N$168
  Bottom 0.381: IC16.42 IC13.42 IC14.42 IC15.42
N$169
  Top 0.381: U$3.9 236.85,17.78 236.85,13.97 U$1.AK1
N$170
  Top 0.381: U$3.10 233.68,17.78 233.68,13.97 U$1.AL1
N$171
  Top 0.381: U$3.11 230.5,17.78 230.5,13.97 U$1.AM1
N$172
  Top 0.381: U$3.12 227.33,17.78 227.33,13.97 U$1.AN1
N$173
  Top 0.381: U$3.13 224.16,17.78 224.16,13.97 U$1.AP1
N$174
  Top 0.381: U$3.14 220.98,17.78 220.98,13.97 U$1.AR1
N$175
  Top 0.381: U$3.15 217.81,17.78 217.81,13.97 U$1.AS1
N$176
  Top 0.381: U$3.16 214.63,17.78 214.63,13.97 U$1.AT1
N$177
  Top 0.381: U$3.17 211.46,17.78 211.46,13.97 U$1.AU1
N$178
  Top 0.381: U$3.18 208.28,17.78 208.28,13.97 U$1.AV1
N$179
  Top 0.381: U$3.8 240.03,17.78 240.03,13.97 U$1.AJ1
N$180
  Top 0.381: U$3.7 243.21,17.78 243.21,13.97 U$1.AH1
N$181
  Top 0.381: U$3.6 246.38,17.78 246.38,13.97 U$1.AF1
N$182
  Top 0.381: U$3.5 249.56,17.78 249.56,13.97 U$1.AE1
N$183
  Top 0.381: U$3.4 252.73,17.78 252.73,13.97 U$1.AD1
N$184
  Top 0.381: U$3.3 255.91,17.78 255.91,13.97 U$1.AC1
N$185
  Top 0.381: U$3.2 259.08,17.78 259.08,13.97 U$1.AB1
N$186
  Top 0.381: U$3.1 262.25,17.78 262.25,16.51 261.62,15.88 261.62,13.97 U$1.AA1
N$187
  Bottom 0.381: U$5.10 232.41,21.59 232.41,13.97 U$1.AL2
N$188
  Bottom 0.381: U$5.11 229.24,21.59 229.24,13.97 U$1.AM2
N$189
  Bottom 0.381: U$5.12 226.06,21.59 226.06,13.97 U$1.AN2
N$190
  Bottom 0.381: U$5.13 222.88,21.59 222.88,13.97 U$1.AP2
N$191
  Bottom 0.381: U$5.14 219.71,21.59 219.71,13.97 U$1.AR2
N$192
  Bottom 0.381: U$5.15 216.53,21.59 216.53,13.97 U$1.AS2
N$193
  Bottom 0.381: U$5.16 213.36,21.59 213.36,13.97 U$1.AT2
N$194
  Bottom 0.381: U$5.9 235.59,21.59 235.59,13.97 U$1.AK2
N$195
  Bottom 0.381: U$5.8 238.76,21.59 238.76,13.97 U$1.AJ2
N$196
  Bottom 0.381: U$5.7 241.94,21.59 241.94,13.97 U$1.AH2
N$197
  Bottom 0.381: U$5.6 245.11,21.59 245.11,13.97 U$1.AF2
N$198
  Bottom 0.381: U$5.5 248.28,21.59 248.28,13.97 U$1.AE2
N$199
  Bottom 0.381: U$5.4 251.46,21.59 251.46,13.97 U$1.AD2
N$200
  Bottom 0.381: IC20.1 IC19.1 IC18.1 IC17.1
N$201
  Bottom 0.381: U$5.17 210.19,21.59 210.19,13.97 U$1.AU2
N$202
  Bottom 0.381: U$5.18 207.01,21.59 207.01,13.97 U$1.AV2
N$203
  Bottom 0.381: U$5.2 257.81,21.59 257.81,13.97 U$1.AB2
N$204
  Bottom 0.381: IC20.2 IC19.2 IC18.2 IC17.2
N$205
  Bottom 0.381: IC20.3 IC19.3 IC18.3 IC17.3
N$206
  Bottom 0.381: IC20.4 IC19.4 IC18.4 IC17.4
N$207
  Bottom 0.381: IC20.5 IC19.5 IC18.5 IC17.5
N$208
  Bottom 0.381: IC20.6 IC19.6 IC18.6 IC17.6
N$209
  Bottom 0.381: IC20.7 IC19.7 IC18.7 IC17.7
N$210
  Bottom 0.381: IC20.8 IC19.8 IC18.8 IC17.8
N$211
  Bottom 0.381: IC20.9 IC19.9 IC18.9 IC17.9
N$212
  Bottom 0.381: IC20.10 IC19.10 IC18.10 IC17.10
N$213
  Bottom 0.381: IC20.11 IC19.11 IC18.11 IC17.11
N$214
  Bottom 0.381: IC20.12 IC19.12 IC18.12 IC17.12
N$215
  Bottom 0.381: IC20.13 IC19.13 IC18.13 IC17.13
N$216
  Bottom 0.381: IC20.14 IC19.14 IC18.14 IC17.14
N$217
  Bottom 0.381: IC20.15 IC19.15 IC18.15 IC17.15
N$218
  Bottom 0.381: IC20.16 IC19.16 IC18.16 IC17.16
N$219
  Bottom 0.381: IC20.17 IC19.17 IC18.17 IC17.17
N$220
  Bottom 0.381: IC20.18 IC19.18 IC18.18 IC17.18
N$221
  Bottom 0.381: IC20.19 IC19.19 IC18.19 IC17.19
N$222
  Bottom 0.381: IC20.20 IC19.20 IC18.20 IC17.20
N$223
  Bottom 0.381: IC20.21 IC19.21 IC18.21 IC17.21
N$224
  Bottom 0.381: IC20.22 IC19.22 IC18.22 IC17.22
N$225
  Bottom 0.381: IC20.23 IC19.23 IC18.23 IC17.23
N$226
  Bottom 0.381: IC20.24 IC19.24 IC18.24 IC17.24
N$227
  Bottom 0.381: IC20.25 IC19.25 IC18.25 IC17.25
N$228
  Bottom 0.381: IC20.26 IC19.26 IC18.26 IC17.26
N$229
  Bottom 0.381: IC20.27 IC19.27 IC18.27 IC17.27
N$230
  Bottom 0.381: IC20.28 IC19.28 IC18.28 IC17.28
N$231
  Bottom 0.381: IC20.29 IC19.29 IC18.29 IC17.29
N$232
  Bottom 0.381: IC20.30 IC19.30 IC18.30 IC17.30
N$233
  Bottom 0.381: IC20.31 IC19.31 IC18.31 IC17.31
N$234
  Bottom 0.381: IC20.32 IC19.32 IC18.32 IC17.32
N$235
  Bottom 0.381: IC20.33 IC19.33 IC18.33 IC17.33
N$236
  Bottom 0.381: IC20.34 IC19.34 IC18.34 IC17.34
N$237
  Bottom 0.381: IC20.35 IC19.35 IC18.35 IC17.35
N$238
  Bottom 0.381: IC20.36 IC19.36 IC18.36 IC17.36
N$239
  Bottom 0.381: IC20.37 IC19.37 IC18.37 IC17.37
N$240
  Bottom 0.381: IC20.38 IC19.38 IC18.38 IC17.38
N$241
  Bottom 0.381: IC20.39 IC19.39 IC18.39 IC17.39
N$242
  Bottom 0.381: IC20.40 IC19.40 IC18.40 IC17.40
N$243
  Bottom 0.381: IC20.41 IC19.41 IC18.41 IC17.41
N$244
  Bottom 0.381: IC20.42 IC19.42 IC18.42 IC17.42
N$245
  Bottom 0.381: IC24.1 IC23.1 IC22.1 IC21.1
N$246
  Bottom 0.381: IC24.2 IC23.2 IC22.2 IC21.2
N$247
  Bottom 0.381: IC24.3 IC23.3 IC22.3 IC21.3
N$248
  Bottom 0.381: IC24.4 IC23.4 IC22.4 IC21.4
N$249
  Bottom 0.381: IC24.5 IC23.5 IC22.5 IC21.5
N$250
  Bottom 0.381: IC24.6 IC23.6 IC22.6 IC21.6
N$251
  Bottom 0.381: IC24.7 IC23.7 IC22.7 IC21.7
N$252
  Bottom 0.381: IC24.8 IC23.8 IC22.8 IC21.8
N$253
  Bottom 0.381: IC24.9 IC23.9 IC22.9 IC21.9
N$254
  Bottom 0.381: IC24.10 IC23.10 IC22.10 IC21.10
N$255
  Bottom 0.381: IC24.11 IC23.11 IC22.11 IC21.11
N$256
  Bottom 0.381: IC24.12 IC23.12 IC22.12 IC21.12
N$257
  Bottom 0.381: IC24.13 IC23.13 IC22.13 IC21.13
N$258
  Bottom 0.381: IC24.14 IC23.14 IC22.14 IC21.14
N$259
  Bottom 0.381: IC24.15 IC23.15 IC22.15 IC21.15
N$260
  Bottom 0.381: IC24.16 IC23.16 IC22.16 IC21.16
N$261
  Bottom 0.381: IC24.17 IC23.17 IC22.17 IC21.17
N$262
  Bottom 0.381: IC24.18 IC23.18 IC22.18 IC21.18
N$263
  Bottom 0.381: IC24.19 IC23.19 IC22.19 IC21.19
N$264
  Bottom 0.381: IC24.20 IC23.20 IC22.20 IC21.20
N$265
  Bottom 0.381: IC24.21 IC23.21 IC22.21 IC21.21
N$266
  Bottom 0.381: IC24.22 IC23.22 IC22.22 IC21.22
N$267
  Bottom 0.381: IC24.23 IC23.23 IC22.23 IC21.23
N$268
  Bottom 0.381: IC24.24 IC23.24 IC22.24 IC21.24
N$269
  Bottom 0.381: IC24.25 IC23.25 IC22.25 IC21.25
N$270
  Bottom 0.381: IC24.26 IC23.26 IC22.26 IC21.26
N$271
  Bottom 0.381: IC24.27 IC23.27 IC22.27 IC21.27
N$272
  Bottom 0.381: IC24.28 IC23.28 IC22.28 IC21.28
N$273
  Bottom 0.381: IC24.29 IC23.29 IC22.29 IC21.29
N$274
  Bottom 0.381: IC24.30 IC23.30 IC22.30 IC21.30
N$275
  Bottom 0.381: IC24.31 IC23.31 IC22.31 IC21.31
N$276
  Bottom 0.381: IC24.32 IC23.32 IC22.32 IC21.32
N$277
  Bottom 0.381: IC24.33 IC23.33 IC22.33 IC21.33
N$278
  Bottom 0.381: IC24.34 IC23.34 IC22.34 IC21.34
N$279
  Bottom 0.381: IC24.35 IC23.35 IC22.35 IC21.35
N$280
  Bottom 0.381: IC24.36 IC23.36 IC22.36 IC21.36
N$281
  Bottom 0.381: IC24.37 IC23.37 IC22.37 IC21.37
N$282
  Bottom 0.381: IC24.38 IC23.38 IC22.38 IC21.38
N$283
  Bottom 0.381: IC24.39 IC23.39 IC22.39 IC21.39
N$284
  Bottom 0.381: IC24.40 IC23.40 IC22.40 IC21.40
N$285
  Bottom 0.381: IC24.41 IC23.41 IC22.41 IC21.41
N$286
  Bottom 0.381: IC24.42 IC23.42 IC22.42 IC21.42
N$287
  Bottom 0.381: IC25.1 IC26.1 IC27.1 IC28.1
N$288
  Bottom 0.381: IC25.2 IC26.2 IC27.2 IC28.2
N$289
  Bottom 0.381: IC25.3 IC26.3 IC27.3 IC28.3
N$290
  Bottom 0.381: IC25.4 IC26.4 IC27.4 IC28.4
N$291
  Bottom 0.381: IC25.5 IC26.5 IC27.5 IC28.5
N$292
  Bottom 0.381: IC25.6 IC26.6 IC27.6 IC28.6
N$293
  Bottom 0.381: IC25.7 IC26.7 IC27.7 IC28.7
N$294
  Bottom 0.381: IC25.8 IC26.8 IC27.8 IC28.8
N$295
  Bottom 0.381: IC25.9 IC26.9 IC27.9 IC28.9
N$296
  Bottom 0.381: IC25.10 IC26.10 IC27.10 IC28.10
N$297
  Bottom 0.381: IC25.11 IC26.11 IC27.11 IC28.11
N$298
  Bottom 0.381: IC25.12 IC26.12 IC27.12 IC28.12
N$299
  Bottom 0.381: IC25.13 IC26.13 IC27.13 IC28.13
N$300
  Bottom 0.381: IC25.14 IC26.14 IC27.14 IC28.14
N$301
  Bottom 0.381: IC25.15 IC26.15 IC27.15 IC28.15
N$302
  Bottom 0.381: IC25.16 IC26.16 IC27.16 IC28.16
N$303
  Bottom 0.381: IC25.17 IC26.17 IC27.17 IC28.17
N$304
  Bottom 0.381: IC25.18 IC26.18 IC27.18 IC28.18
N$305
  Bottom 0.381: IC25.19 IC26.19 IC27.19 IC28.19
N$306
  Bottom 0.381: IC25.20 IC26.20 IC27.20 IC28.20
N$307
  Bottom 0.381: IC25.21 IC26.21 IC27.21 IC28.21
N$308
  Bottom 0.381: IC25.22 IC26.22 IC27.22 IC28.22
N$309
  Bottom 0.381: IC25.23 IC26.23 IC27.23 IC28.23
N$310
  Bottom 0.381: IC25.24 IC26.24 IC27.24 IC28.24
N$311
  Bottom 0.381: IC25.25 IC26.25 IC27.25 IC28.25
N$312
  Bottom 0.381: IC25.26 IC26.26 IC27.26 IC28.26
N$313
  Bottom 0.381: IC25.27 IC26.27 IC27.27 IC28.27
N$314
  Bottom 0.381: IC25.28 IC26.28 IC27.28 IC28.28
N$315
  Bottom 0.381: IC25.29 IC26.29 IC27.29 IC28.29
N$316
  Bottom 0.381: IC25.30 IC26.30 IC27.30 IC28.30
N$317
  Bottom 0.381: IC25.31 IC26.31 IC27.31 IC28.31
N$318
  Bottom 0.381: IC25.32 IC26.32 IC27.32 IC28.32
N$319
  Bottom 0.381: IC25.33 IC26.33 IC27.33 IC28.33
N$320
  Bottom 0.381: IC25.34 IC26.34 IC27.34 IC28.34
N$321
  Bottom 0.381: IC25.35 IC26.35 IC27.35 IC28.35
N$322
  Bottom 0.381: IC25.36 IC26.36 IC27.36 IC28.36
N$323
  Bottom 0.381: IC25.37 IC26.37 IC27.37 IC28.37
N$324
  Bottom 0.381: IC25.38 IC26.38 IC27.38 IC28.38
N$325
  Bottom 0.381: IC25.39 IC26.39 IC27.39 IC28.39
N$326
  Bottom 0.381: IC25.40 IC26.40 IC27.40 IC28.40
N$327
  Bottom 0.381: IC25.41 IC26.41 IC27.41 IC28.41
N$328
  Bottom 0.381: IC25.42 IC26.42 IC27.42 IC28.42
N$329
  Bottom 0.381: IC29.1 IC30.1 IC31.1 IC32.1
N$330
  Bottom 0.381: IC29.2 IC30.2 IC31.2 IC32.2
N$331
  Bottom 0.381: IC29.3 IC30.3 IC31.3 IC32.3
N$332
  Bottom 0.381: IC29.4 IC30.4 IC31.4 IC32.4
N$333
  Bottom 0.381: IC29.5 IC30.5 IC31.5 IC32.5
N$334
  Bottom 0.381: IC29.6 IC30.6 IC31.6 IC32.6
N$335
  Bottom 0.381: IC29.7 IC30.7 IC31.7 IC32.7
N$336
  Bottom 0.381: IC29.8 IC30.8 IC31.8 IC32.8
N$337
  Bottom 0.381: IC29.9 IC30.9 IC31.9 IC32.9
N$338
  Bottom 0.381: IC29.10 IC30.10 IC31.10 IC32.10
N$339
  Bottom 0.381: IC29.11 IC30.11 IC31.11 IC32.11
N$340
  Bottom 0.381: IC29.12 IC30.12 IC31.12 IC32.12
N$341
  Bottom 0.381: IC29.13 IC30.13 IC31.13 IC32.13
N$342
  Bottom 0.381: IC29.14 IC30.14 IC31.14 IC32.14
N$343
  Bottom 0.381: IC29.15 IC30.15 IC31.15 IC32.15
N$344
  Bottom 0.381: IC29.16 IC30.16 IC31.16 IC32.16
N$345
  Bottom 0.381: IC29.17 IC30.17 IC31.17 IC32.17
N$346
  Bottom 0.381: IC29.18 IC30.18 IC31.18 IC32.18
N$347
  Bottom 0.381: IC29.19 IC30.19 IC31.19 IC32.19
N$348
  Bottom 0.381: IC29.20 IC30.20 IC31.20 IC32.20
N$349
  Bottom 0.381: IC29.21 IC30.21 IC31.21 IC32.21
N$350
  Bottom 0.381: IC29.22 IC30.22 IC31.22 IC32.22
N$351
  Bottom 0.381: IC29.23 IC30.23 IC31.23 IC32.23
N$352
  Bottom 0.381: IC29.24 IC30.24 IC31.24 IC32.24
N$353
  Bottom 0.381: IC29.25 IC30.25 IC31.25 IC32.25
N$354
  Bottom 0.381: IC29.26 IC30.26 IC31.26 IC32.26
N$355
  Bottom 0.381: IC29.27 IC30.27 IC31.27 IC32.27
N$356
  Bottom 0.381: IC29.28 IC30.28 IC31.28 IC32.28
N$357
  Bottom 0.381: IC29.29 IC30.29 IC31.29 IC32.29
N$358
  Bottom 0.381: IC29.30 IC30.30 IC31.30 IC32.30
N$359
  Bottom 0.381: IC29.31 IC30.31 IC31.31 IC32.31
N$360
  Bottom 0.381: IC29.32 IC30.32 IC31.32 IC32.32
N$361
  Bottom 0.381: IC29.33 IC30.33 IC31.33 IC32.33
N$362
  Bottom 0.381: IC29.34 IC30.34 IC31.34 IC32.34
N$363
  Bottom 0.381: IC29.35 IC30.35 IC31.35 IC32.35
N$364
  Bottom 0.381: IC29.36 IC30.36 IC31.36 IC32.36
N$365
  Bottom 0.381: IC29.37 IC30.37 IC31.37 IC32.37
N$366
  Bottom 0.381: IC29.38 IC30.38 IC31.38 IC32.38
N$367
  Bottom 0.381: IC29.39 IC30.39 IC31.39 IC32.39
N$368
  Bottom 0.381: IC29.40 IC30.40 IC31.40 IC32.40
N$369
  Bottom 0.381: IC29.41 IC30.41 IC31.41 IC32.41
N$370
  Bottom 0.381: IC29.42 IC30.42 IC31.42 IC32.42
N$371
  Bottom 0.381: IC33.1 IC34.1 IC35.1 IC36.1
N$372
  Bottom 0.381: IC33.2 IC34.2 IC35.2 IC36.2
N$373
  Top 0.381: U$6.18 138.43,17.78 138.43,13.97 U$1.BV1
N$374
  Top 0.381: U$6.17 141.6,17.78 141.6,13.97 U$1.BU1
N$375
  Top 0.381: U$6.16 144.78,17.78 144.78,13.97 U$1.BT1
N$376
  Top 0.381: U$6.15 147.96,17.78 147.96,13.97 U$1.BS1
N$377
  Top 0.381: U$6.14 151.13,17.78 151.13,13.97 U$1.BR1
N$378
  Top 0.381: U$6.13 154.31,17.78 154.31,13.97 U$1.BP1
N$379
  Top 0.381: U$6.12 157.48,17.78 157.48,13.97 U$1.BN1
N$380
  Top 0.381: U$6.11 160.66,17.78 160.66,13.97 U$1.BM1
N$381
  Top 0.381: U$6.10 163.83,17.78 163.83,13.97 U$1.BL1
N$382
  Top 0.381: U$6.9 167,17.78 167,13.97 U$1.BK1
N$383
  Top 0.381: U$6.8 170.18,17.78 170.18,13.97 U$1.BJ1
N$384
  Top 0.381: U$6.7 173.35,17.78 173.35,13.97 U$1.BH1
N$385
  Top 0.381: U$6.6 176.53,17.78 176.53,13.97 U$1.BF1
N$386
  Top 0.381: U$6.5 179.71,17.78 179.71,13.97 U$1.BE1
N$387
  Top 0.381: U$6.4 182.88,17.78 182.88,13.97 U$1.BD1
N$388
  Top 0.381: U$6.3 186.06,17.78 186.06,13.97 U$1.BC1
N$389
  Top 0.381: U$6.2 189.23,17.78 189.23,13.97 U$1.BB1
N$390
  Top 0.381: U$6.1 192.41,17.78 192.41,16.51 191.77,15.88 191.77,13.97 U$1.BA1
N$391
  Bottom 0.381: U$7.18 137.16,21.59 137.16,13.97 U$1.BV2
N$392
  Bottom 0.381: U$7.17 140.34,21.59 140.34,13.97 U$1.BU2
N$393
  Bottom 0.381: U$7.16 143.51,21.59 143.51,13.97 U$1.BT2
N$394
  Bottom 0.381: U$7.15 146.69,21.59 146.69,13.97 U$1.BS2
N$395
  Bottom 0.381: U$7.14 149.86,21.59 149.86,13.97 U$1.BR2
N$396
  Bottom 0.381: U$7.13 153.03,21.59 153.03,13.97 U$1.BP2
N$397
  Bottom 0.381: U$7.12 156.21,21.59 156.21,13.97 U$1.BN2
N$398
  Bottom 0.381: U$7.11 159.38,21.59 159.38,13.97 U$1.BM2
N$399
  Bottom 0.381: U$7.10 162.56,21.59 162.56,13.97 U$1.BL2
N$400
  Bottom 0.381: U$7.9 165.74,21.59 165.74,13.97 U$1.BK2
N$401
  Bottom 0.381: U$7.8 168.91,21.59 168.91,13.97 U$1.BJ2
N$402
  Bottom 0.381: U$7.7 172.09,21.59 172.09,13.97 U$1.BH2
N$403
  Bottom 0.381: U$7.6 175.26,21.59 175.26,13.97 U$1.BF2
N$404
  Bottom 0.381: U$7.5 178.44,21.59 178.44,13.97 U$1.BE2
N$405
  Bottom 0.381: U$7.4 181.61,21.59 181.61,13.97 U$1.BD2
N$406
  Bottom 0.381: U$7.3 184.78,21.59 184.78,13.97 U$1.BC2
N$407
  Bottom 0.381: U$7.2 187.96,21.59 187.96,13.97 U$1.BB2
N$408
  Bottom 0.381: U$7.1 191.13,21.59 191.13,13.97 U$1.BA2
N$409
  Top 0.381: U$9.18 74.93,17.78 74.93,13.97 U$1.CV1
N$410
  Top 0.381: U$9.17 78.11,17.78 78.11,13.97 U$1.CU1
N$411
  Top 0.381: U$9.16 81.28,17.78 81.28,13.97 U$1.CT1
N$412
  Top 0.381: U$9.15 84.45,17.78 84.45,13.97 U$1.CS1
N$413
  Top 0.381: U$9.14 87.63,17.78 87.63,13.97 U$1.CR1
N$414
  Top 0.381: U$9.13 90.81,17.78 90.81,13.97 U$1.CP1
N$415
  Top 0.381: U$9.12 93.98,17.78 93.98,13.97 U$1.CN1
N$416
  Top 0.381: U$9.11 97.16,17.78 97.16,13.97 U$1.CM1
N$417
  Top 0.381: U$9.10 100.33,17.78 100.33,13.97 U$1.CL1
N$418
  Top 0.381: U$9.9 103.5,17.78 103.5,13.97 U$1.CK1
N$419
  Top 0.381: U$9.8 106.68,17.78 106.68,13.97 U$1.CJ1
N$420
  Top 0.381: U$9.7 109.86,17.78 109.86,13.97 U$1.CH1
N$421
  Top 0.381: U$9.6 113.03,17.78 113.03,13.97 U$1.CF1
N$422
  Top 0.381: U$9.5 116.2,17.78 116.2,13.97 U$1.CE1
N$423
  Top 0.381: U$9.4 119.38,17.78 119.38,13.97 U$1.CD1
N$424
  Top 0.381: U$9.3 122.56,17.78 122.56,13.97 U$1.CC1
N$425
  Top 0.381: U$9.2 125.73,17.78 125.73,13.97 U$1.CB1
N$426
  Top 0.381: U$9.1 128.91,17.78 128.91,16.51 128.27,15.88 128.27,13.97 U$1.CA1
N$427
  Bottom 0.381: U$10.18 73.66,21.59 73.66,13.97 U$1.CV2
N$428
  Bottom 0.381: U$10.17 76.83,21.59 76.83,13.97 U$1.CU2
N$429
  Bottom 0.381: U$10.16 80.01,21.59 80.01,13.97 U$1.CT2
N$430
  Bottom 0.381: U$10.15 83.19,21.59 83.19,13.97 U$1.CS2
N$431
  Bottom 0.381: U$10.14 86.36,21.59 86.36,13.97 U$1.CR2
N$432
  Bottom 0.381: U$10.13 89.53,21.59 89.53,13.97 U$1.CP2
N$433
  Bottom 0.381: U$10.12 92.71,21.59 92.71,13.97 U$1.CN2
N$434
  Bottom 0.381: U$10.11 95.89,21.59 95.89,13.97 U$1.CM2
N$435
  Bottom 0.381: U$10.10 99.06,21.59 99.06,13.97 U$1.CL2
N$436
  Bottom 0.381: U$10.9 102.23,21.59 102.23,13.97 U$1.CK2
N$437
  Bottom 0.381: U$10.8 105.41,21.59 105.41,13.97 U$1.CJ2
N$438
  Bottom 0.381: U$10.7 108.58,21.59 108.58,13.97 U$1.CH2
N$439
  Bottom 0.381: U$10.6 111.76,21.59 111.76,13.97 U$1.CF2
N$440
  Bottom 0.381: U$10.5 114.94,21.59 114.94,13.97 U$1.CE2
N$441
  Bottom 0.381: U$10.4 118.11,21.59 118.11,13.97 U$1.CD2
N$442
  Bottom 0.381: U$10.3 121.28,21.59 121.28,13.97 U$1.CC2
N$443
  Bottom 0.381: U$10.2 124.46,21.59 124.46,13.97 U$1.CB2
N$444
  Bottom 0.381: U$10.1 127.64,21.59 127.64,13.97 U$1.CA2
N$445
  Top 0.381: U$11.18 5.08,17.78 5.08,13.97 U$1.DV1
N$446
  Top 0.381: U$11.17 8.26,17.78 8.26,13.97 U$1.DU1
N$447
  Top 0.381: U$11.16 11.43,17.78 11.43,13.97 U$1.DT1
N$448
  Top 0.381: U$11.15 14.61,17.78 14.61,13.97 U$1.DS1
N$449
  Top 0.381: U$11.14 17.78,17.78 17.78,13.97 U$1.DR1
N$450
  Top 0.381: U$11.13 20.95,17.78 20.95,13.97 U$1.DP1
N$451
  Top 0.381: U$11.12 24.13,17.78 24.13,13.97 U$1.DN1
N$452
  Top 0.381: U$11.11 27.3,17.78 27.3,13.97 U$1.DM1
N$453
  Top 0.381: U$11.10 30.48,17.78 30.48,13.97 U$1.DL1
N$454
  Top 0.381: U$11.9 33.66,17.78 33.66,13.97 U$1.DK1
N$455
  Top 0.381: U$11.8 36.83,17.78 36.83,13.97 U$1.DJ1
N$456
  Top 0.381: U$11.7 40.01,17.78 40.01,13.97 U$1.DH1
N$457
  Top 0.381: U$11.6 43.18,17.78 43.18,13.97 U$1.DF1
N$458
  Top 0.381: U$11.5 46.35,17.78 46.35,13.97 U$1.DE1
N$459
  Top 0.381: U$11.4 49.53,17.78 49.53,13.97 U$1.DD1
N$460
  Top 0.381: U$11.3 52.7,17.78 52.7,13.97 U$1.DC1
N$461
  Top 0.381: U$11.2 55.88,17.78 55.88,13.97 U$1.DB1
N$462
  Top 0.381: U$11.1 59.05,17.78 59.05,16.51 58.42,15.88 58.42,13.97 U$1.DA1
N$463
  Bottom 0.381: U$12.18 3.81,21.59 3.81,13.97 U$1.DV2
N$464
  Bottom 0.381: U$12.17 6.99,21.59 6.99,13.97 U$1.DU2
N$465
  Bottom 0.381: U$12.16 10.16,21.59 10.16,13.97 U$1.DT2
N$466
  Bottom 0.381: U$12.15 13.34,21.59 13.34,13.97 U$1.DS2
N$467
  Bottom 0.381: U$12.14 16.51,21.59 16.51,13.97 U$1.DR2
N$468
  Bottom 0.381: U$12.13 19.68,21.59 19.68,13.97 U$1.DP2
N$469
  Bottom 0.381: U$12.12 22.86,21.59 22.86,13.97 U$1.DN2
N$470
  Bottom 0.381: U$12.11 26.04,21.59 26.04,13.97 U$1.DM2
N$471
  Bottom 0.381: U$12.10 29.21,21.59 29.21,13.97 U$1.DL2
N$472
  Bottom 0.381: U$12.9 32.38,21.59 32.38,13.97 U$1.DK2
N$473
  Bottom 0.381: U$12.8 35.56,21.59 35.56,13.97 U$1.DJ2
N$474
  Bottom 0.381: U$12.7 38.73,21.59 38.73,13.97 U$1.DH2
N$475
  Bottom 0.381: U$12.6 41.91,21.59 41.91,13.97 U$1.DF2
N$476
  Bottom 0.381: U$12.5 45.09,21.59 45.09,13.97 U$1.DE2
N$477
  Bottom 0.381: U$12.4 48.26,21.59 48.26,13.97 U$1.DD2
N$478
  Bottom 0.381: U$12.3 51.44,21.59 51.44,13.97 U$1.DC2
N$479
  Bottom 0.381: U$12.2 54.61,21.59 54.61,13.97 U$1.DB2
N$480
  Bottom 0.381: U$12.1 57.78,21.59 57.78,13.97 U$1.DA2
N$481
  Bottom 0.381: IC33.3 IC34.3 IC35.3 IC36.3
N$482
  Bottom 0.381: IC33.4 IC34.4 IC35.4 IC36.4
N$483
  Bottom 0.381: IC33.5 IC34.5 IC35.5 IC36.5
N$484
  Bottom 0.381: IC33.6 IC34.6 IC35.6 IC36.6
N$485
  Bottom 0.381: IC33.7 IC34.7 IC35.7 IC36.7
N$486
  Bottom 0.381: IC33.8 IC34.8 IC35.8 IC36.8
N$487
  Bottom 0.381: IC33.9 IC34.9 IC35.9 IC36.9
N$488
  Bottom 0.381: IC33.10 IC34.10 IC35.10 IC36.10
N$489
  Bottom 0.381: IC33.11 IC34.11 IC35.11 IC36.11
N$490
  Bottom 0.381: IC33.12 IC34.12 IC35.12 IC36.12
N$491
  Bottom 0.381: IC33.13 IC34.13 IC35.13 IC36.13
N$492
  Bottom 0.381: IC33.14 IC34.14 IC35.14 IC36.14
N$493
  Bottom 0.381: IC33.15 IC34.15 IC35.15 IC36.15
N$494
  Bottom 0.381: IC33.16 IC34.16 IC35.16 IC36.16
N$495
  Bottom 0.381: IC33.17 IC34.17 IC35.17 IC36.17
N$496
  Bottom 0.381: IC33.18 IC34.18 IC35.18 IC36.18
N$497
  Bottom 0.381: IC33.19 IC34.19 IC35.19 IC36.19
N$498
  Bottom 0.381: IC33.20 IC34.20 IC35.20 IC36.20
N$499
  Bottom 0.381: IC33.21 IC34.21 IC35.21 IC36.21
N$500
  Bottom 0.381: IC33.22 IC34.22 IC35.22 IC36.22
N$501
  Bottom 0.381: IC33.23 IC34.23 IC35.23 IC36.23
N$502
  Bottom 0.381: IC33.24 IC34.24 IC35.24 IC36.24
N$503
  Bottom 0.381: IC33.25 IC34.25 IC35.25 IC36.25
N$504
  Bottom 0.381: IC33.26 IC34.26 IC35.26 IC36.26
N$505
  Bottom 0.381: IC33.27 IC34.27 IC35.27 IC36.27
N$506
  Bottom 0.381: IC33.28 IC34.28 IC35.28 IC36.28
N$507
  Bottom 0.381: IC33.29 IC34.29 IC35.29 IC36.29
N$508
  Bottom 0.381: IC33.30 IC34.30 IC35.30 IC36.30
N$509
  Bottom 0.381: IC33.31 IC34.31 IC35.31 IC36.31
N$510
  Bottom 0.381: IC33.32 IC34.32 IC35.32 IC36.32
N$511
  Bottom 0.381: IC33.33 IC34.33 IC35.33 IC36.33
N$512
  Bottom 0.381: IC33.34 IC34.34 IC35.34 IC36.34
N$513
  Bottom 0.381: IC33.35 IC34.35 IC35.35 IC36.35
N$514
  Bottom 0.381: IC33.36 IC34.36 IC35.36 IC36.36
N$515
  Bottom 0.381: IC33.37 IC34.37 IC35.37 IC36.37
N$516
  Bottom 0.381: IC33.38 IC34.38 IC35.38 IC36.38
N$517
  Bottom 0.381: IC33.39 IC34.39 IC35.39 IC36.39
N$518
  Bottom 0.381: IC33.40 IC34.40 IC35.40 IC36.40
N$519
  Bottom 0.381: IC33.41 IC34.41 IC35.41 IC36.41
N$520
  Bottom 0.381: IC33.42 IC34.42 IC35.42 IC36.42
N$521
  Bottom 0.381: IC37.1 IC38.1 IC39.1 IC40.1
N$522
  Bottom 0.381: IC37.2 IC38.2 IC39.2 IC40.2
N$523
  Bottom 0.381: IC37.3 IC38.3 IC39.3 IC40.3
N$524
  Bottom 0.381: IC37.4 IC38.4 IC39.4 IC40.4
N$525
  Bottom 0.381: IC37.5 IC38.5 IC39.5 IC40.5
N$526
  Bottom 0.381: IC37.6 IC38.6 IC39.6 IC40.6
N$527
  Bottom 0.381: IC37.7 IC38.7 IC39.7 IC40.7
N$528
  Bottom 0.381: IC37.8 IC38.8 IC39.8 IC40.8
N$529
  Bottom 0.381: IC37.9 IC38.9 IC39.9 IC40.9
N$530
  Bottom 0.381: IC37.10 IC38.10 IC39.10 IC40.10
N$531
  Bottom 0.381: IC37.11 IC38.11 IC39.11 IC40.11
N$532
  Bottom 0.381: IC37.12 IC38.12 IC39.12 IC40.12
N$533
  Bottom 0.381: IC37.13 IC38.13 IC39.13 IC40.13
N$534
  Bottom 0.381: IC37.14 IC38.14 IC39.14 IC40.14
N$535
  Bottom 0.381: IC37.15 IC38.15 IC39.15 IC40.15
N$536
  Bottom 0.381: IC37.16 IC38.16 IC39.16 IC40.16
N$537
  Bottom 0.381: IC37.17 IC38.17 IC39.17 IC40.17
N$538
  Bottom 0.381: IC37.18 IC38.18 IC39.18 IC40.18
N$539
  Bottom 0.381: IC37.19 IC38.19 IC39.19 IC40.19
N$540
  Bottom 0.381: IC37.20 IC38.20 IC39.20 IC40.20
N$541
  Bottom 0.381: IC37.21 IC38.21 IC39.21 IC40.21
N$542
  Bottom 0.381: IC37.22 IC38.22 IC39.22 IC40.22
N$543
  Bottom 0.381: IC37.23 IC38.23 IC39.23 IC40.23
N$544
  Bottom 0.381: IC37.24 IC38.24 IC39.24 IC40.24
N$545
  Bottom 0.381: IC37.25 IC38.25 IC39.25 IC40.25
N$546
  Bottom 0.381: IC37.26 IC38.26 IC39.26 IC40.26
N$547
  Bottom 0.381: IC37.27 IC38.27 IC39.27 IC40.27
N$548
  Bottom 0.381: IC37.28 IC38.28 IC39.28 IC40.28
N$549
  Bottom 0.381: IC37.29 IC38.29 IC39.29 IC40.29
N$550
  Bottom 0.381: IC37.30 IC38.30 IC39.30 IC40.30
N$551
  Bottom 0.381: IC37.31 IC38.31 IC39.31 IC40.31
N$552
  Bottom 0.381: IC37.32 IC38.32 IC39.32 IC40.32
N$553
  Bottom 0.381: IC37.33 IC38.33 IC39.33 IC40.33
N$554
  Bottom 0.381: IC37.34 IC38.34 IC39.34 IC40.34
N$555
  Bottom 0.381: IC37.35 IC38.35 IC39.35 IC40.35
N$556
  Bottom 0.381: IC37.36 IC38.36 IC39.36 IC40.36
N$557
  Bottom 0.381: IC37.37 IC38.37 IC39.37 IC40.37
N$558
  Bottom 0.381: IC37.38 IC38.38 IC39.38 IC40.38
N$559
  Bottom 0.381: IC37.39 IC38.39 IC39.39 IC40.39
N$560
  Bottom 0.381: IC37.40 IC38.40 IC39.40 IC40.40
N$561
  Bottom 0.381: IC37.41 IC38.41 IC39.41 IC40.41
N$562
  Bottom 0.381: IC37.42 IC38.42 IC39.42 IC40.42
N$563
  Bottom 0.381: IC41.1 IC42.1 IC43.1 IC44.1
N$564
  Bottom 0.381: IC41.2 IC42.2 IC43.2 IC44.2
N$565
  Bottom 0.381: IC41.3 IC42.3 IC43.3 IC44.3
N$566
  Bottom 0.381: IC41.4 IC42.4 IC43.4 IC44.4
N$567
  Bottom 0.381: IC41.5 IC42.5 IC43.5 IC44.5
N$568
  Bottom 0.381: IC41.6 IC42.6 IC43.6 IC44.6
N$569
  Bottom 0.381: IC41.7 IC42.7 IC43.7 IC44.7
N$570
  Bottom 0.381: IC41.8 IC42.8 IC43.8 IC44.8
N$571
  Bottom 0.381: IC41.9 IC42.9 IC43.9 IC44.9
N$572
  Bottom 0.381: IC41.10 IC42.10 IC43.10 IC44.10
N$573
  Bottom 0.381: IC41.11 IC42.11 IC43.11 IC44.11
N$574
  Bottom 0.381: IC41.12 IC42.12 IC43.12 IC44.12
N$575
  Bottom 0.381: IC41.13 IC42.13 IC43.13 IC44.13
N$576
  Bottom 0.381: IC41.14 IC42.14 IC43.14 IC44.14
N$577
  Bottom 0.381: IC41.15 IC42.15 IC43.15 IC44.15
N$578
  Bottom 0.381: IC41.16 IC42.16 IC43.16 IC44.16
N$579
  Bottom 0.381: IC41.17 IC42.17 IC43.17 IC44.17
N$580
  Bottom 0.381: IC41.18 IC42.18 IC43.18 IC44.18
N$581
  Bottom 0.381: IC41.19 IC42.19 IC43.19 IC44.19
N$582
  Bottom 0.381: IC41.20 IC42.20 IC43.20 IC44.20
N$583
  Bottom 0.381: IC41.21 IC42.21 IC43.21 IC44.21
N$584
  Bottom 0.381: IC41.22 IC42.22 IC43.22 IC44.22
N$585
  Bottom 0.381: IC41.23 IC42.23 IC43.23 IC44.23
N$586
  Bottom 0.381: IC41.24 IC42.24 IC43.24 IC44.24
N$587
  Bottom 0.381: IC41.25 IC42.25 IC43.25 IC44.25
N$588
  Bottom 0.381: IC41.26 IC42.26 IC43.26 IC44.26
N$589
  Bottom 0.381: IC41.27 IC42.27 IC43.27 IC44.27
N$590
  Bottom 0.381: IC41.28 IC42.28 IC43.28 IC44.28
N$591
  Bottom 0.381: IC41.29 IC42.29 IC43.29 IC44.29
N$592
  Bottom 0.381: IC41.30 IC42.30 IC43.30 IC44.30
N$593
  Bottom 0.381: IC41.31 IC42.31 IC43.31 IC44.31
N$594
  Bottom 0.381: IC41.32 IC42.32 IC43.32 IC44.32
N$595
  Bottom 0.381: IC41.33 IC42.33 IC43.33 IC44.33
N$596
  Bottom 0.381: IC41.34 IC42.34 IC43.34 IC44.34
N$597
  Bottom 0.381: IC41.35 IC42.35 IC43.35 IC44.35
N$598
  Bottom 0.381: IC41.36 IC42.36 IC43.36 IC44.36
N$599
  Bottom 0.381: IC41.37 IC42.37 IC43.37 IC44.37
N$600
  Bottom 0.381: IC41.38 IC42.38 IC43.38 IC44.38
N$601
  Bottom 0.381: IC41.39 IC42.39 IC43.39 IC44.39
N$602
  Bottom 0.381: IC41.40 IC42.40 IC43.40 IC44.40
N$603
  Bottom 0.381: IC41.41 IC42.41 IC43.41 IC44.41
N$604
  Bottom 0.381: IC41.42 IC42.42 IC43.42 IC44.42
N$605
  Bottom 0.381: IC45.1 IC46.1 IC47.1 IC48.1
N$606
  Bottom 0.381: IC45.2 IC46.2 IC47.2 IC48.2
N$607
  Bottom 0.381: IC45.3 IC46.3 IC47.3 IC48.3
N$608
  Bottom 0.381: IC45.4 IC46.4 IC47.4 IC48.4
N$609
  Bottom 0.381: IC45.5 IC46.5 IC47.5 IC48.5
N$610
  Bottom 0.381: IC45.6 IC46.6 IC47.6 IC48.6
N$611
  Bottom 0.381: IC45.7 IC46.7 IC47.7 IC48.7
N$612
  Bottom 0.381: IC45.8 IC46.8 IC47.8 IC48.8
N$613
  Bottom 0.381: IC45.9 IC46.9 IC47.9 IC48.9
N$614
  Bottom 0.381: IC45.10 IC46.10 IC47.10 IC48.10
N$615
  Bottom 0.381: IC45.11 IC46.11 IC47.11 IC48.11
N$616
  Bottom 0.381: IC45.12 IC46.12 IC47.12 IC48.12
N$617
  Bottom 0.381: IC45.13 IC46.13 IC47.13 IC48.13
N$618
  Bottom 0.381: IC45.14 IC46.14 IC47.14 IC48.14
N$619
  Bottom 0.381: IC45.15 IC46.15 IC47.15 IC48.15
N$620
  Bottom 0.381: IC45.16 IC46.16 IC47.16 IC48.16
N$621
  Bottom 0.381: IC45.17 IC46.17 IC47.17 IC48.17
N$622
  Bottom 0.381: IC45.18 IC46.18 IC47.18 IC48.18
N$623
  Bottom 0.381: IC45.19 IC46.19 IC47.19 IC48.19
N$624
  Bottom 0.381: IC45.20 IC46.20 IC47.20 IC48.20
N$625
  Bottom 0.381: IC45.21 IC46.21 IC47.21 IC48.21
N$626
  Bottom 0.381: IC45.22 IC46.22 IC47.22 IC48.22
N$627
  Bottom 0.381: IC45.23 IC46.23 IC47.23 IC48.23
N$628
  Bottom 0.381: IC45.24 IC46.24 IC47.24 IC48.24
N$629
  Bottom 0.381: IC45.25 IC46.25 IC47.25 IC48.25
N$630
  Bottom 0.381: IC45.26 IC46.26 IC47.26 IC48.26
N$631
  Bottom 0.381: IC45.27 IC46.27 IC47.27 IC48.27
N$632
  Bottom 0.381: IC45.28 IC46.28 IC47.28 IC48.28
N$633
  Bottom 0.381: IC45.29 IC46.29 IC47.29 IC48.29
N$634
  Bottom 0.381: IC45.30 IC46.30 IC47.30 IC48.30
N$635
  Bottom 0.381: IC45.31 IC46.31 IC47.31 IC48.31
N$636
  Bottom 0.381: IC45.32 IC46.32 IC47.32 IC48.32
N$637
  Bottom 0.381: IC45.33 IC46.33 IC47.33 IC48.33
N$638
  Bottom 0.381: IC45.34 IC46.34 IC47.34 IC48.34
N$639
  Bottom 0.381: IC45.35 IC46.35 IC47.35 IC48.35
N$640
  Bottom 0.381: IC45.36 IC46.36 IC47.36 IC48.36
N$641
  Bottom 0.381: IC45.37 IC46.37 IC47.37 IC48.37
N$642
  Bottom 0.381: IC45.38 IC46.38 IC47.38 IC48.38
N$643
  Bottom 0.381: IC45.39 IC46.39 IC47.39 IC48.39
N$644
  Bottom 0.381: IC45.40 IC46.40 IC47.40 IC48.40
N$645
  Bottom 0.381: IC45.41 IC46.41 IC47.41 IC48.41
N$646
  Bottom 0.381: IC45.42 IC46.42 IC47.42 IC48.42
N$647
  Bottom 0.381: IC49.1 IC50.1 IC51.1 IC52.1
N$648
  Bottom 0.381: IC49.2 IC50.2 IC51.2 IC52.2
N$649
  Bottom 0.381: IC49.3 IC50.3 IC51.3 IC52.3
N$650
  Bottom 0.381: IC49.4 IC50.4 IC51.4 IC52.4
N$651
  Bottom 0.381: IC49.5 IC50.5 IC51.5 IC52.5
N$652
  Bottom 0.381: IC49.6 IC50.6 IC51.6 IC52.6
N$653
  Bottom 0.381: IC49.7 IC50.7 IC51.7 IC52.7
N$654
  Bottom 0.381: IC49.8 IC50.8 IC51.8 IC52.8
N$655
  Bottom 0.381: IC49.9 IC50.9 IC51.9 IC52.9
N$656
  Bottom 0.381: IC49.10 IC50.10 IC51.10 IC52.10
N$657
  Bottom 0.381: IC49.11 IC50.11 IC51.11 IC52.11
N$658
  Bottom 0.381: IC49.12 IC50.12 IC51.12 IC52.12
N$659
  Bottom 0.381: IC49.13 IC50.13 IC51.13 IC52.13
N$660
  Bottom 0.381: IC49.14 IC50.14 IC51.14 IC52.14
N$661
  Bottom 0.381: IC49.15 IC50.15 IC51.15 IC52.15
N$662
  Bottom 0.381: IC49.16 IC50.16 IC51.16 IC52.16
N$663
  Bottom 0.381: IC49.17 IC50.17 IC51.17 IC52.17
N$664
  Bottom 0.381: IC49.18 IC50.18 IC51.18 IC52.18
N$665
  Bottom 0.381: IC49.19 IC50.19 IC51.19 IC52.19
N$666
  Bottom 0.381: IC49.20 IC50.20 IC51.20 IC52.20
N$667
  Bottom 0.381: IC49.21 IC50.21 IC51.21 IC52.21
N$668
  Bottom 0.381: IC49.22 IC50.22 IC51.22 IC52.22
N$669
  Bottom 0.381: IC49.23 IC50.23 IC51.23 IC52.23
N$670
  Bottom 0.381: IC49.24 IC50.24 IC51.24 IC52.24
N$671
  Bottom 0.381: IC49.25 IC50.25 IC51.25 IC52.25
N$672
  Bottom 0.381: IC49.26 IC50.26 IC51.26 IC52.26
N$673
  Bottom 0.381: IC49.27 IC50.27 IC51.27 IC52.27
N$674
  Bottom 0.381: IC49.28 IC50.28 IC51.28 IC52.28
N$675
  Bottom 0.381: IC49.29 IC50.29 IC51.29 IC52.29
N$676
  Bottom 0.381: IC49.30 IC50.30 IC51.30 IC52.30
N$677
  Bottom 0.381: IC49.31 IC50.31 IC51.31 IC52.31
N$678
  Bottom 0.381: IC49.32 IC50.32 IC51.32 IC52.32
N$679
  Bottom 0.381: IC49.33 IC50.33 IC51.33 IC52.33
N$680
  Bottom 0.381: IC49.34 IC50.34 IC51.34 IC52.34
N$681
  Bottom 0.381: IC49.35 IC50.35 IC51.35 IC52.35
N$682
  Bottom 0.381: IC49.36 IC50.36 IC51.36 IC52.36
N$683
  Bottom 0.381: IC49.37 IC50.37 IC51.37 IC52.37
N$684
  Bottom 0.381: IC49.38 IC50.38 IC51.38 IC52.38
N$685
  Bottom 0.381: IC49.39 IC50.39 IC51.39 IC52.39
N$686
  Bottom 0.381: IC49.40 IC50.40 IC51.40 IC52.40
N$687
  Bottom 0.381: IC49.41 IC50.41 IC51.41 IC52.41
N$688
  Bottom 0.381: IC49.42 IC50.42 IC51.42 IC52.42
N$689
  Bottom 0.381: IC53.1 IC54.1 IC55.1 IC56.1
N$690
  Bottom 0.381: IC53.2 IC54.2 IC55.2 IC56.2
N$691
  Bottom 0.381: IC53.3 IC54.3 IC55.3 IC56.3
N$692
  Bottom 0.381: IC53.4 IC54.4 IC55.4 IC56.4
N$693
  Bottom 0.381: IC53.5 IC54.5 IC55.5 IC56.5
N$694
  Bottom 0.381: IC53.6 IC54.6 IC55.6 IC56.6
N$695
  Bottom 0.381: IC53.7 IC54.7 IC55.7 IC56.7
N$696
  Bottom 0.381: IC53.8 IC54.8 IC55.8 IC56.8
N$697
  Bottom 0.381: IC53.9 IC54.9 IC55.9 IC56.9
N$698
  Bottom 0.381: IC53.10 IC54.10 IC55.10 IC56.10
N$699
  Bottom 0.381: IC53.11 IC54.11 IC55.11 IC56.11
N$700
  Bottom 0.381: IC53.12 IC54.12 IC55.12 IC56.12
N$701
  Bottom 0.381: IC53.13 IC54.13 IC55.13 IC56.13
N$702
  Bottom 0.381: IC53.14 IC54.14 IC55.14 IC56.14
N$703
  Bottom 0.381: IC53.15 IC54.15 IC55.15 IC56.15
N$704
  Bottom 0.381: IC53.16 IC54.16 IC55.16 IC56.16
N$705
  Bottom 0.381: IC53.17 IC54.17 IC55.17 IC56.17
N$706
  Bottom 0.381: IC53.18 IC54.18 IC55.18 IC56.18
N$707
  Bottom 0.381: IC53.19 IC54.19 IC55.19 IC56.19
N$708
  Bottom 0.381: IC53.20 IC54.20 IC55.20 IC56.20
N$709
  Bottom 0.381: IC53.21 IC54.21 IC55.21 IC56.21
N$710
  Bottom 0.381: IC53.22 IC54.22 IC55.22 IC56.22
N$711
  Bottom 0.381: IC53.23 IC54.23 IC55.23 IC56.23
N$712
  Bottom 0.381: IC53.24 IC54.24 IC55.24 IC56.24
N$713
  Bottom 0.381: IC53.25 IC54.25 IC55.25 IC56.25
N$714
  Bottom 0.381: IC53.26 IC54.26 IC55.26 IC56.26
N$715
  Bottom 0.381: IC53.27 IC54.27 IC55.27 IC56.27
N$716
  Bottom 0.381: IC53.28 IC54.28 IC55.28 IC56.28
N$717
  Bottom 0.381: IC53.29 IC54.29 IC55.29 IC56.29
N$718
  Bottom 0.381: IC53.30 IC54.30 IC55.30 IC56.30
N$719
  Bottom 0.381: IC53.31 IC54.31 IC55.31 IC56.31
N$720
  Bottom 0.381: IC53.32 IC54.32 IC55.32 IC56.32
N$721
  Bottom 0.381: IC53.33 IC54.33 IC55.33 IC56.33
N$722
  Bottom 0.381: IC53.34 IC54.34 IC55.34 IC56.34
N$723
